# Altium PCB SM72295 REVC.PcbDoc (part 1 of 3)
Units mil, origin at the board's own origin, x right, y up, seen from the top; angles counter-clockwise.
Board outline 8660 x 6340 mil, 6 copper layers (Top Layer, MidLayer1, MidLayer2, MidLayer3, MidLayer4, Bottom Layer), stack 118 mil thick; 253 components, 96 nets, 606 pads, 1472 vias.
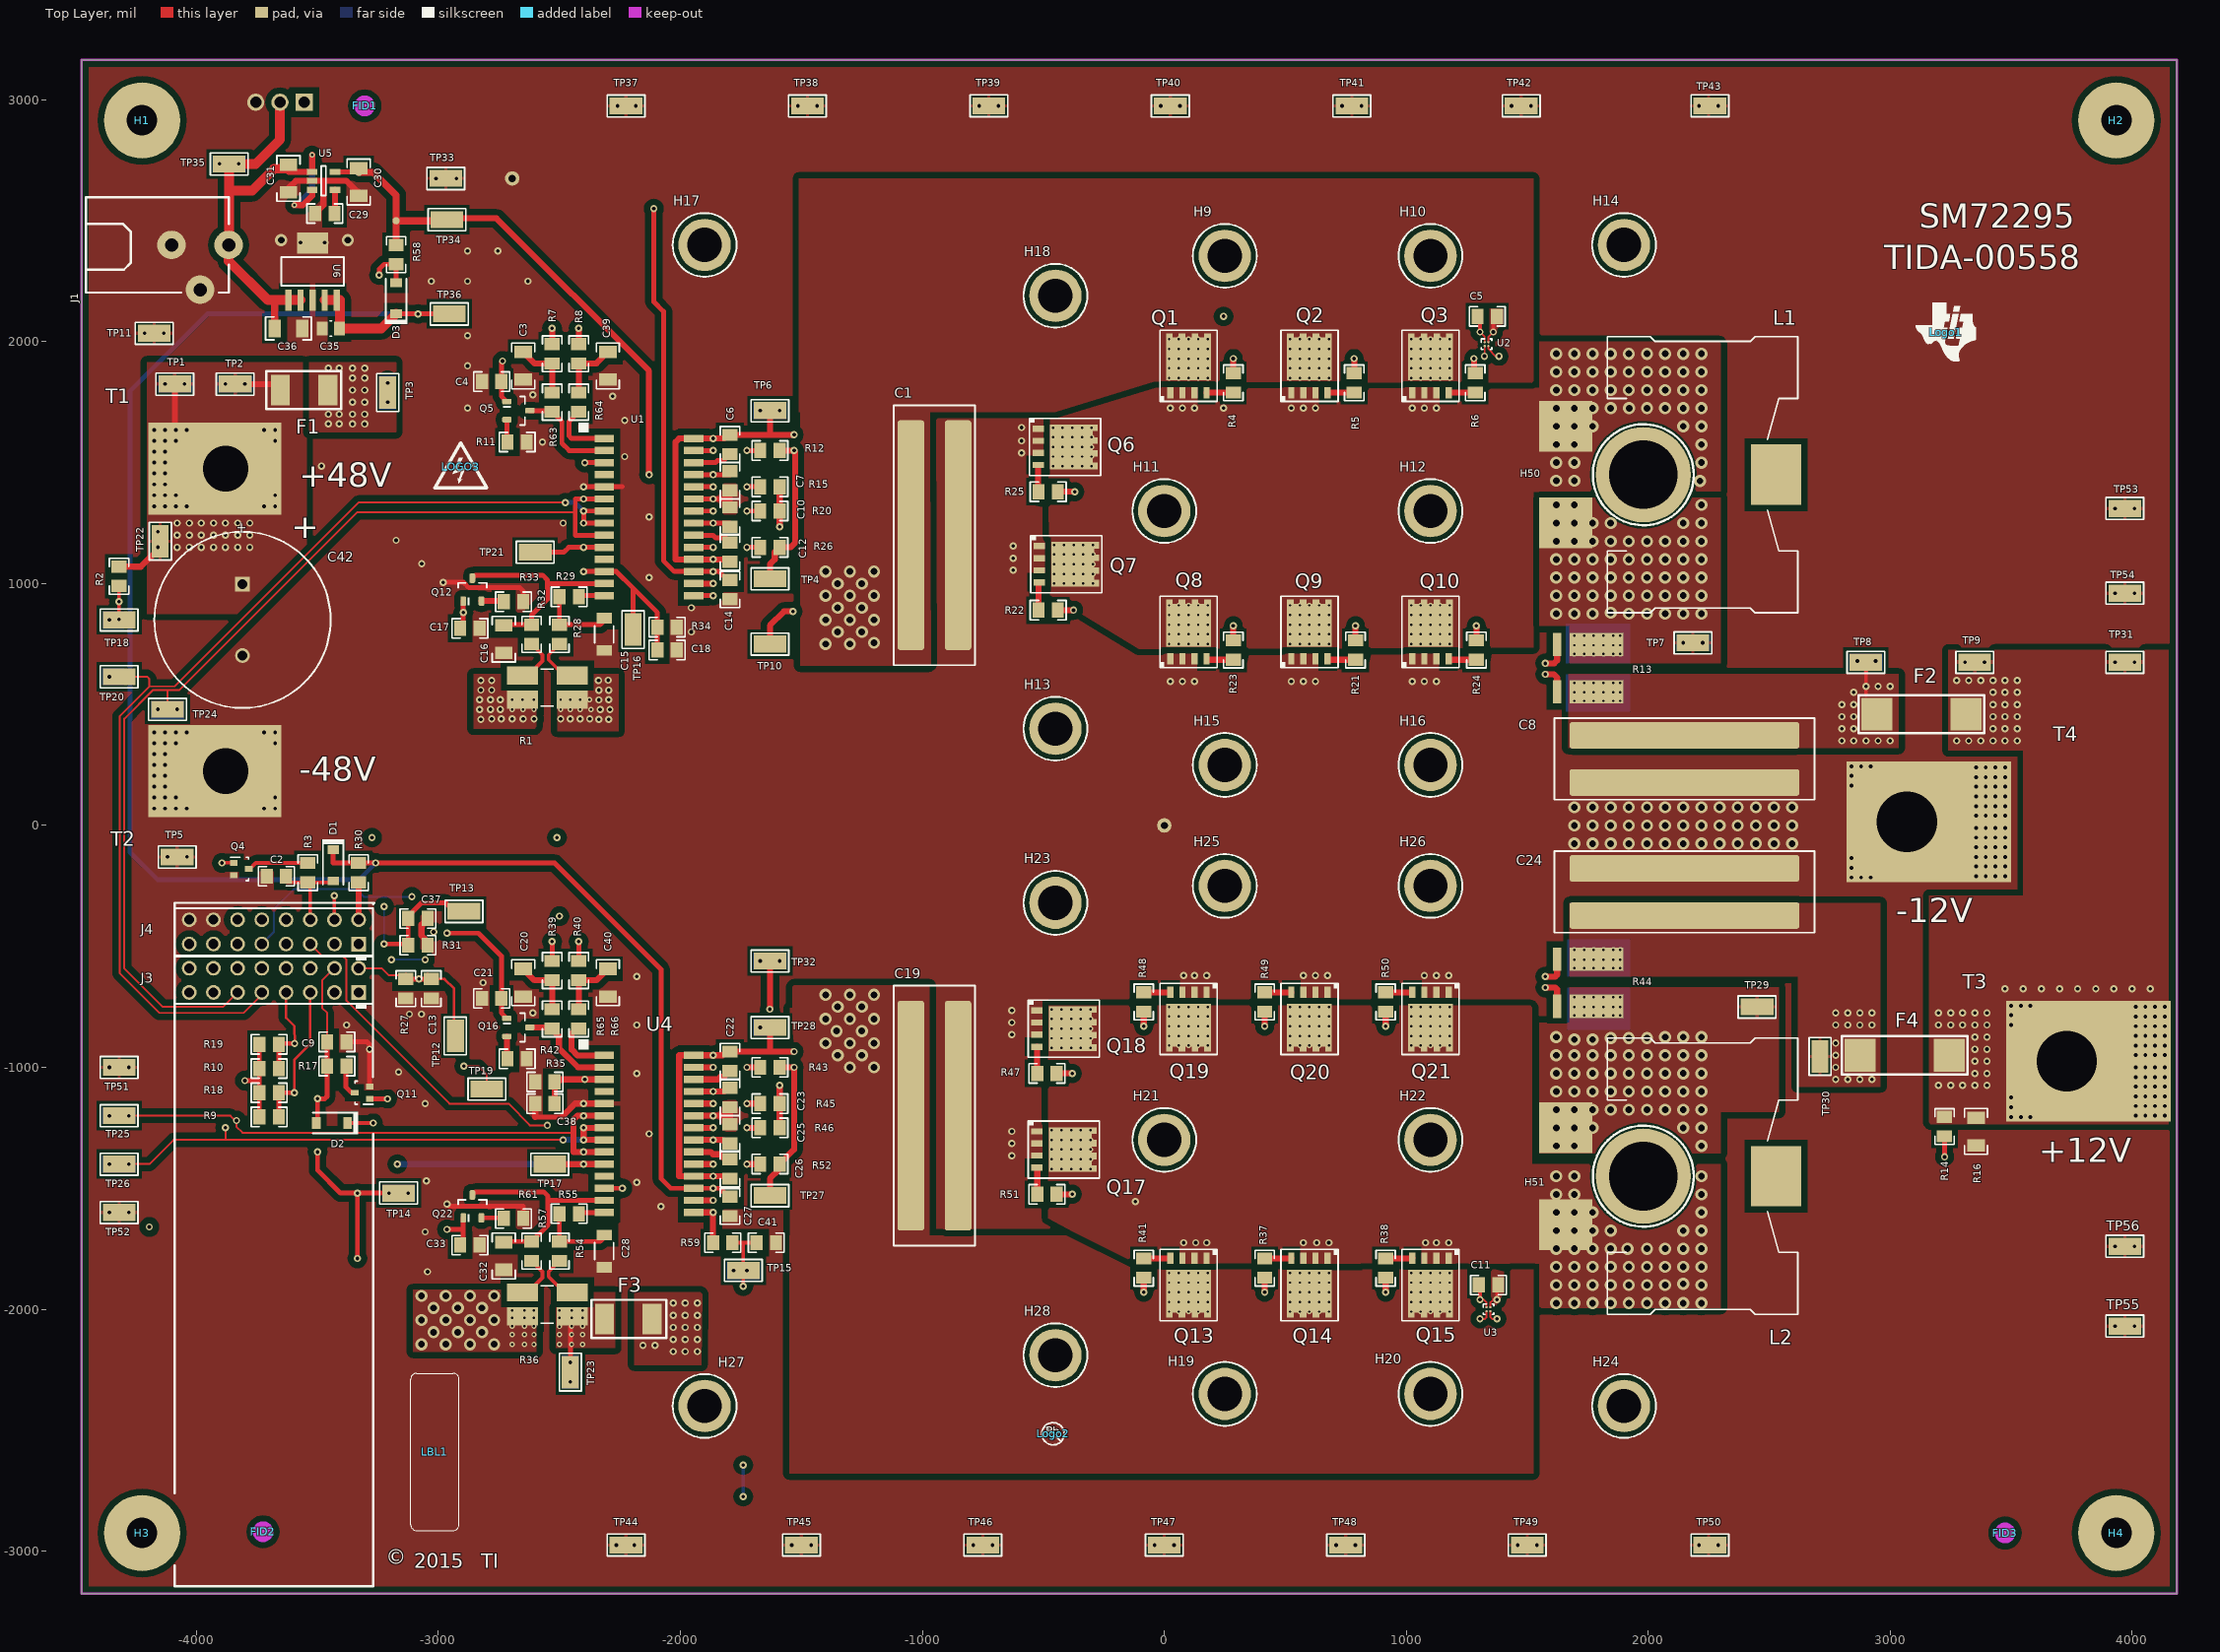
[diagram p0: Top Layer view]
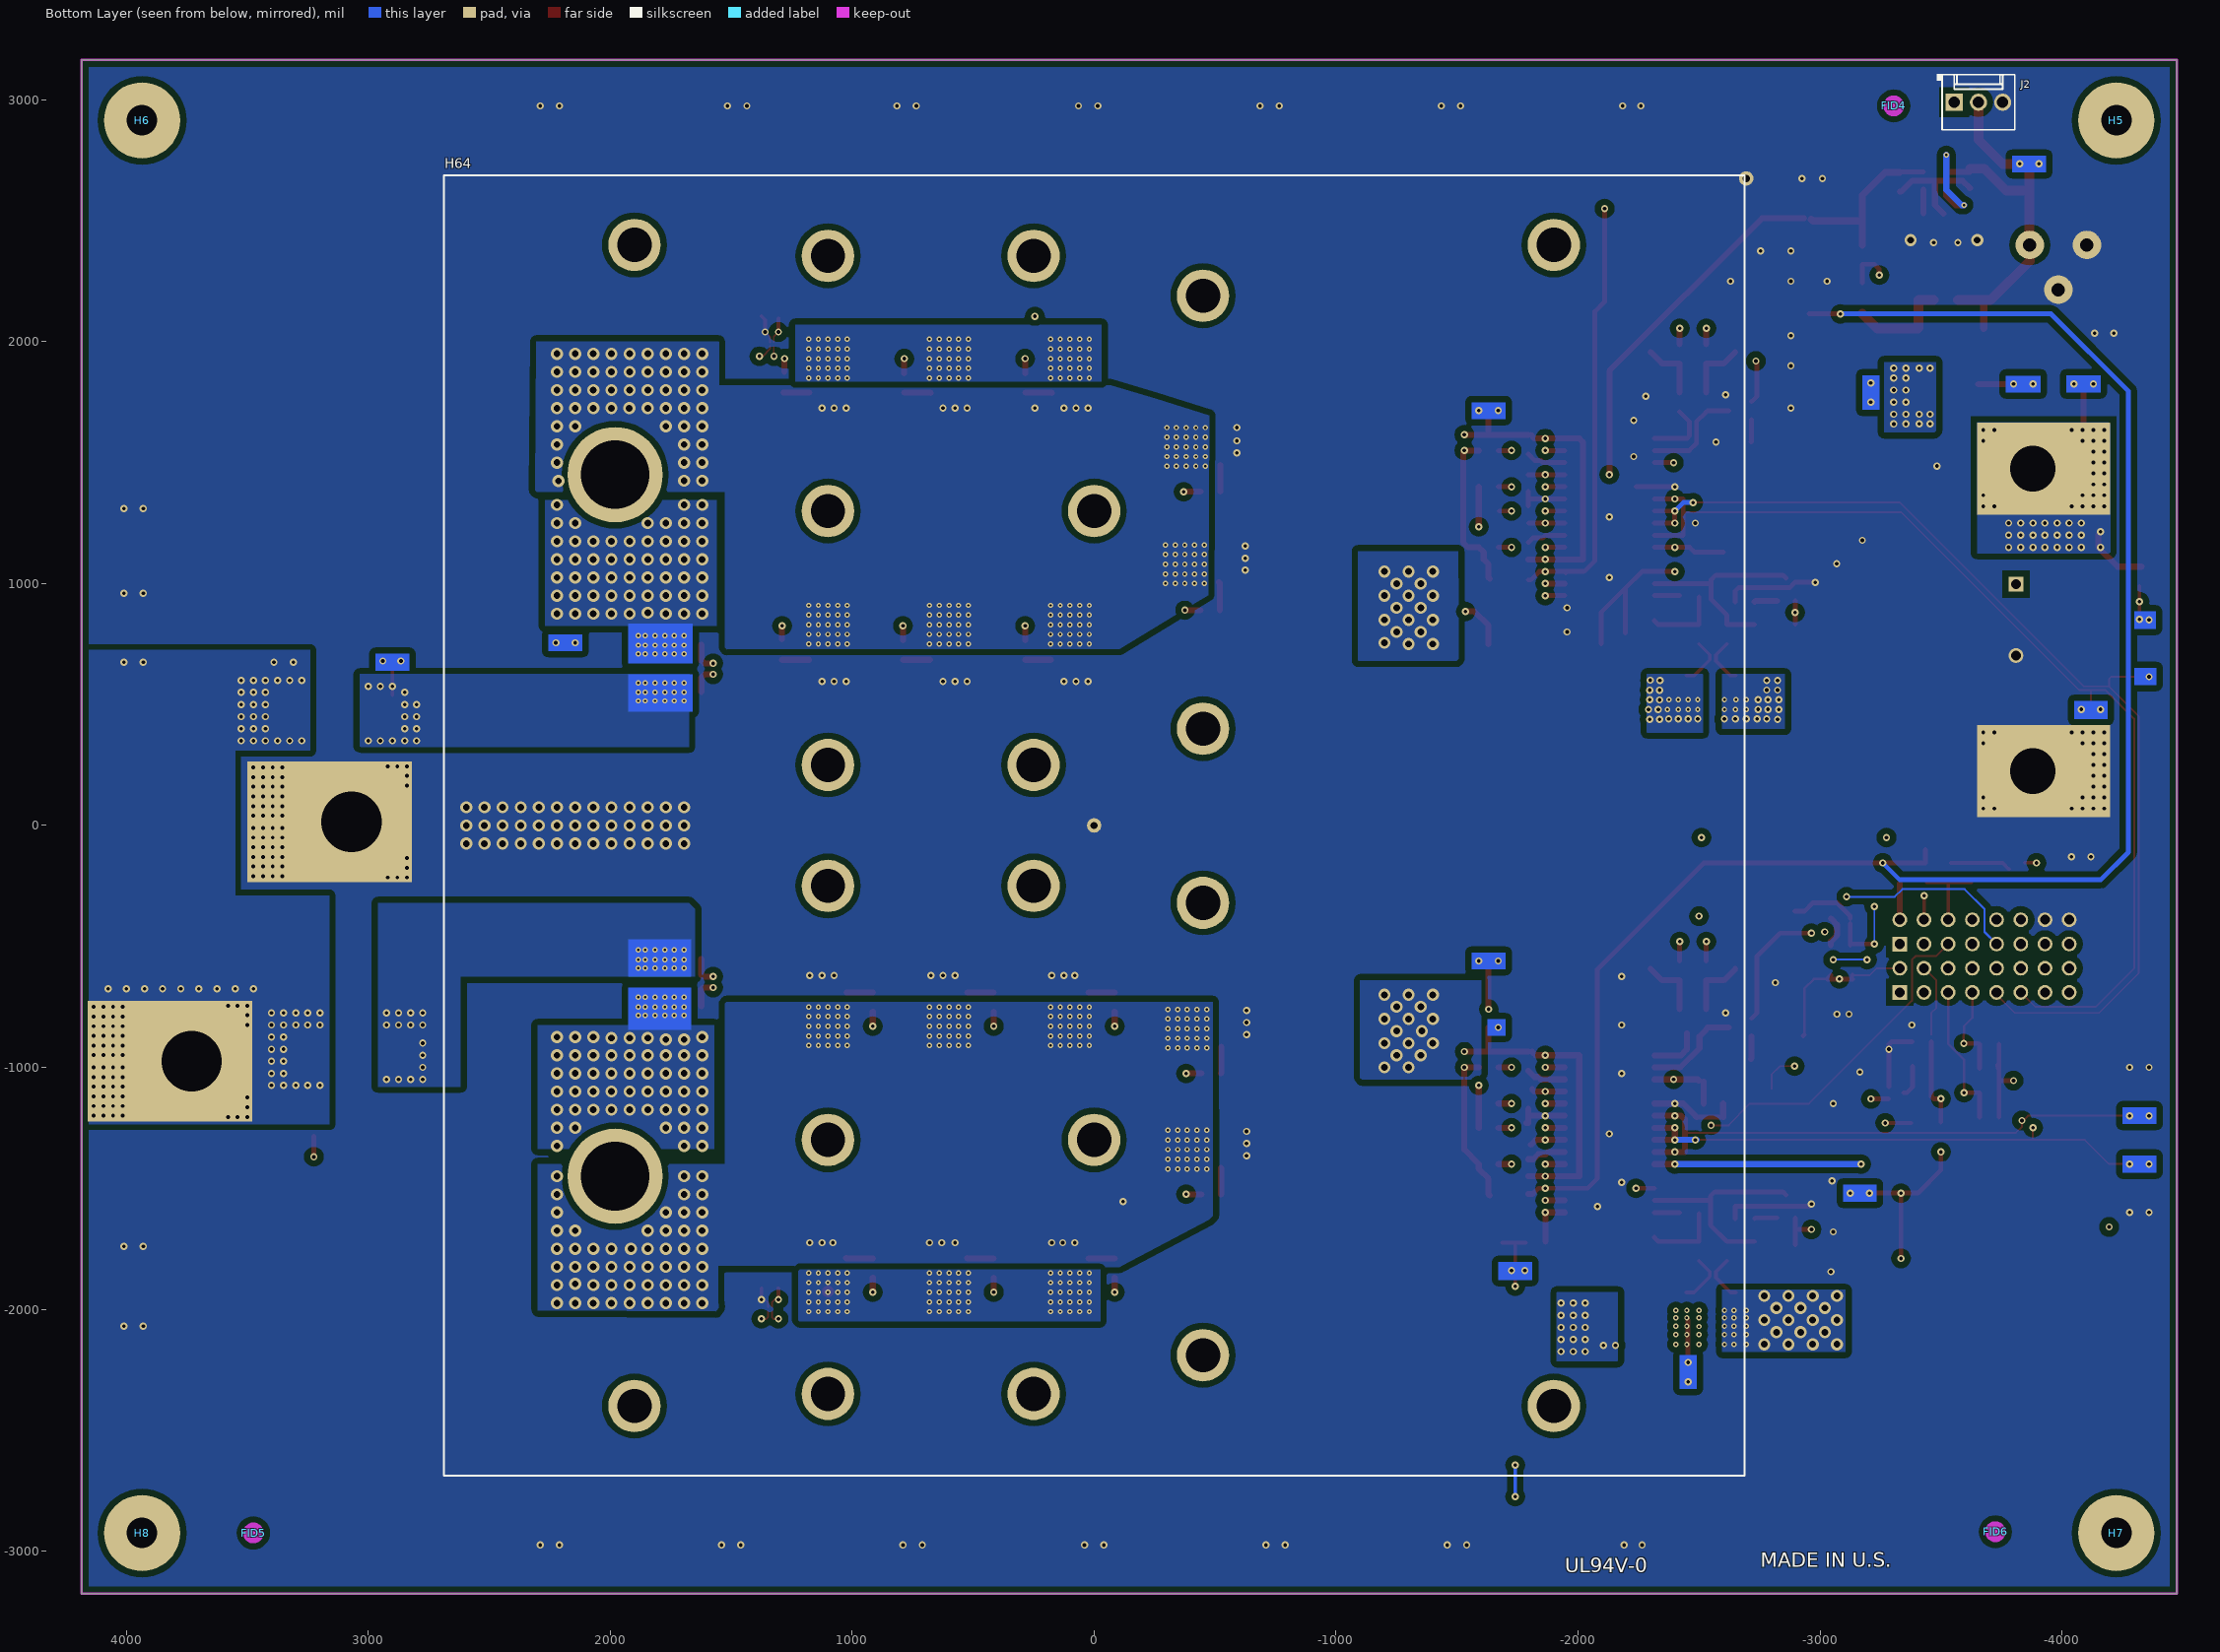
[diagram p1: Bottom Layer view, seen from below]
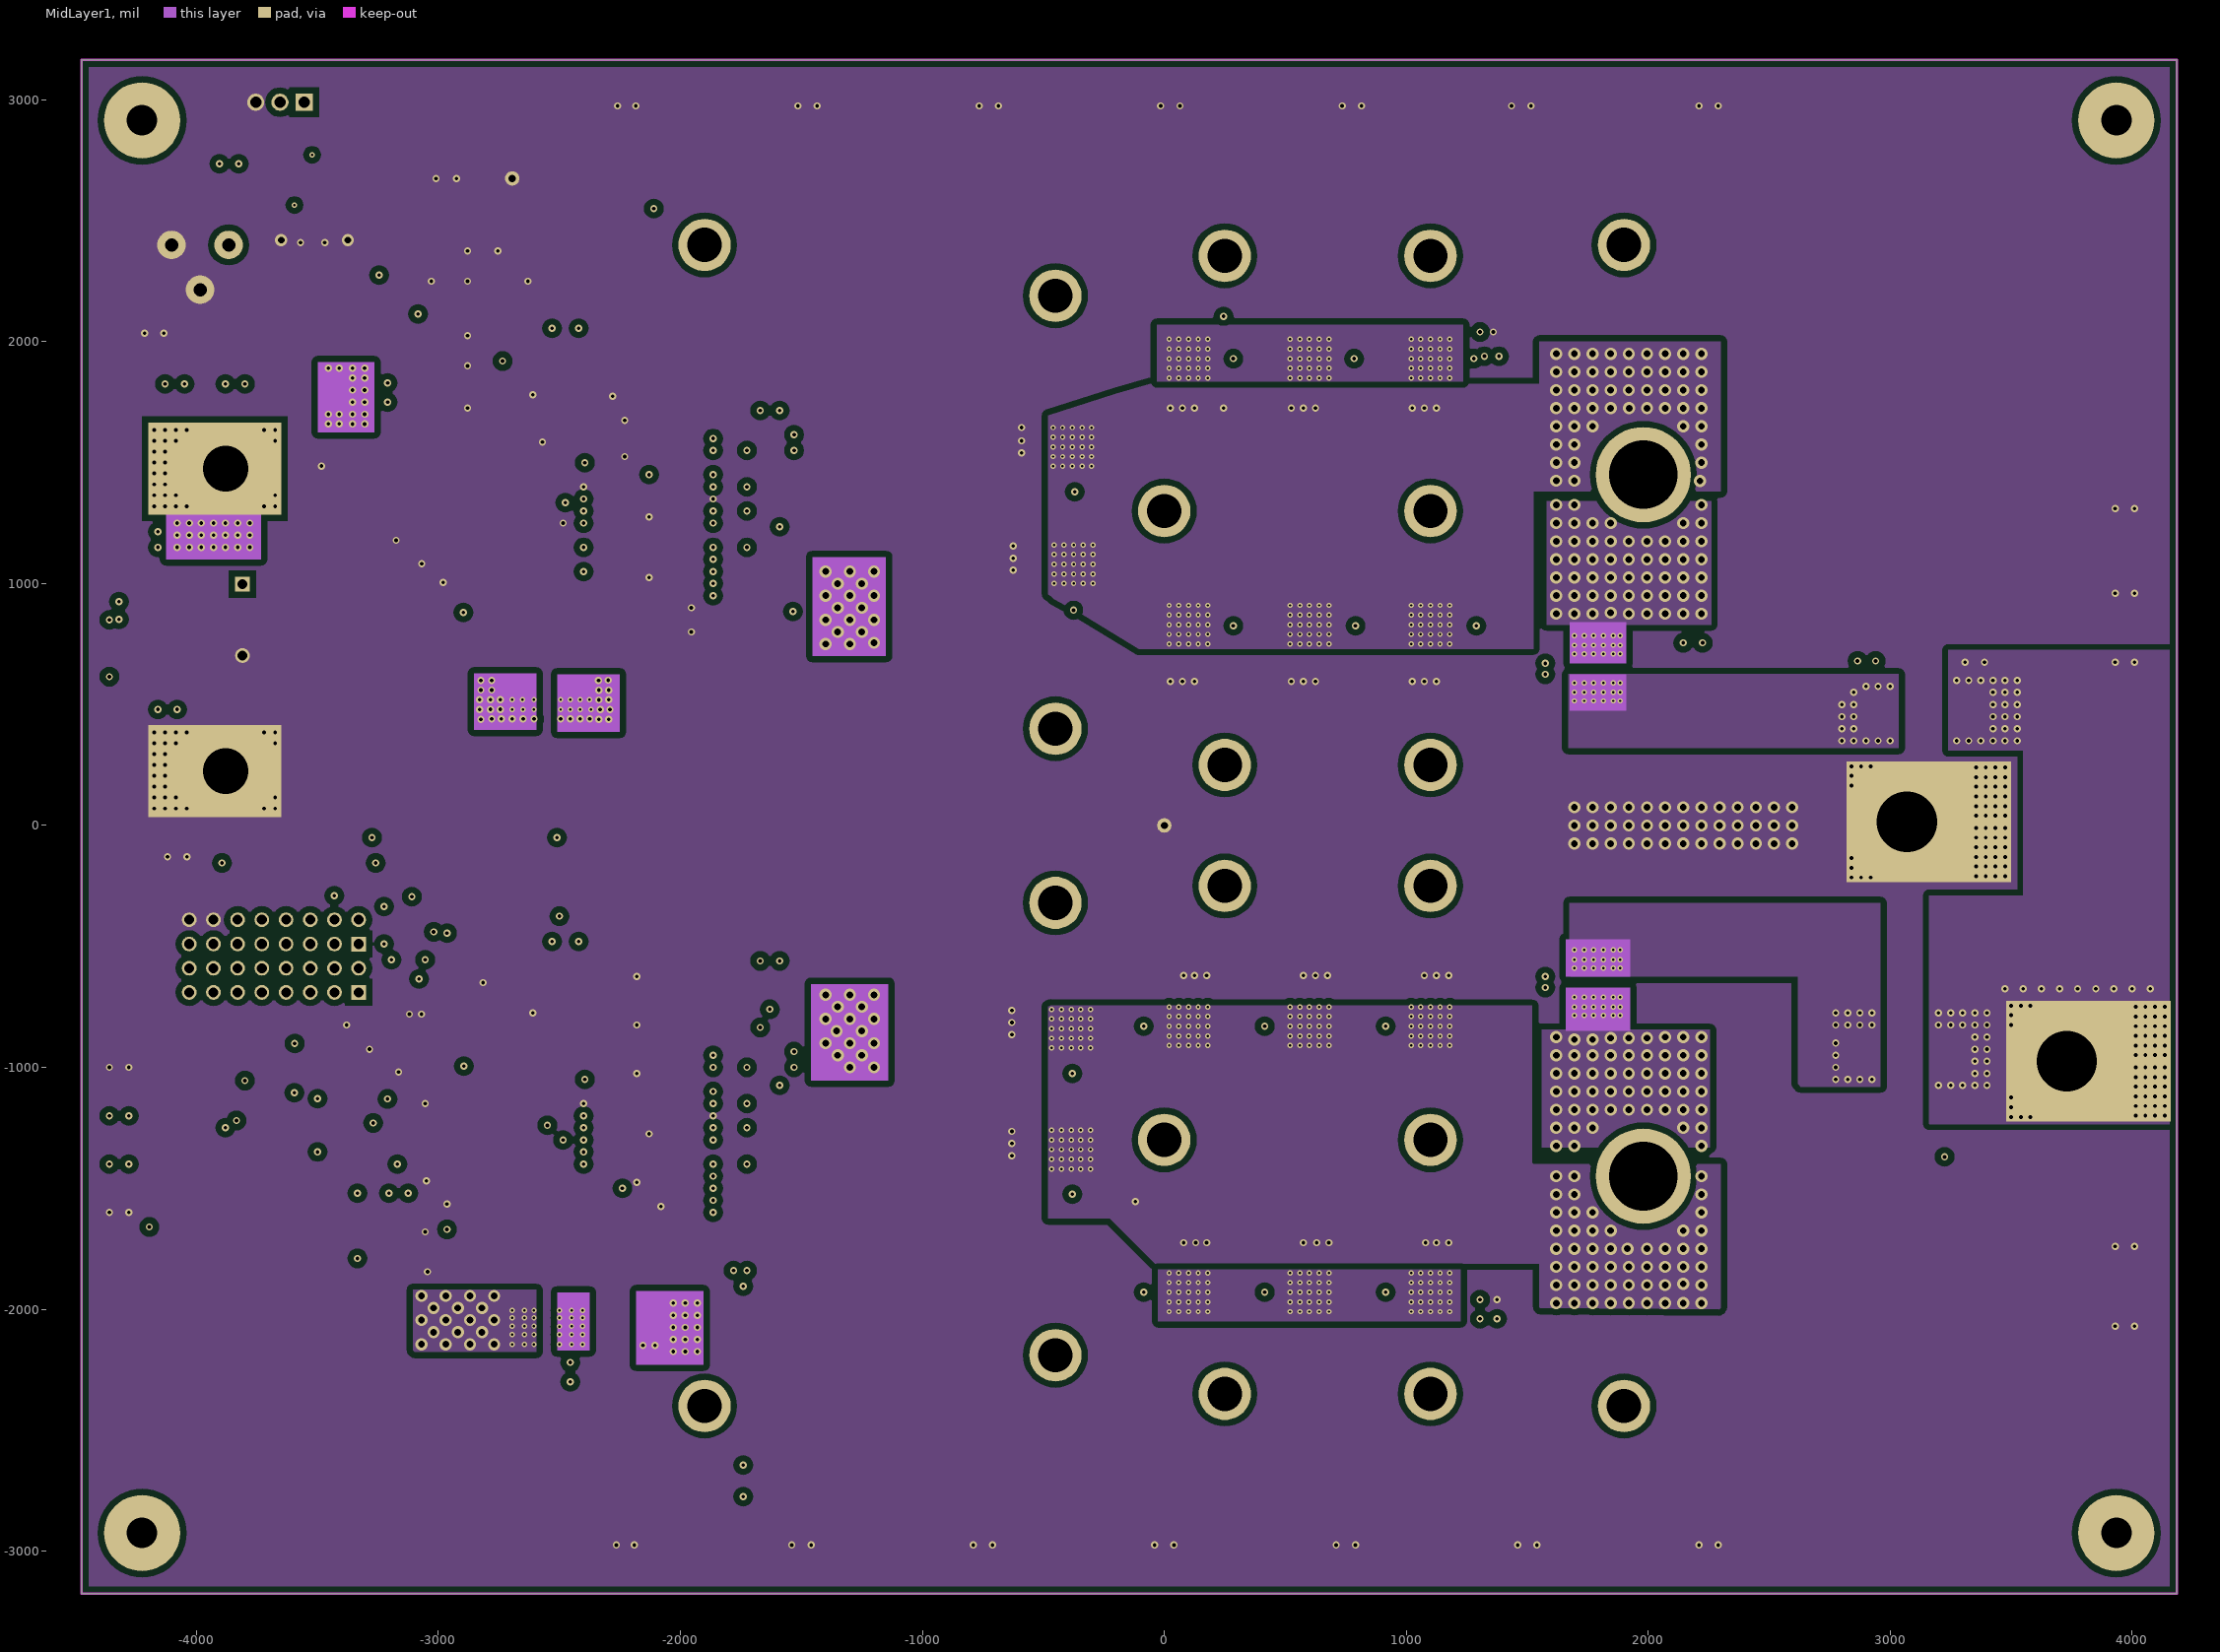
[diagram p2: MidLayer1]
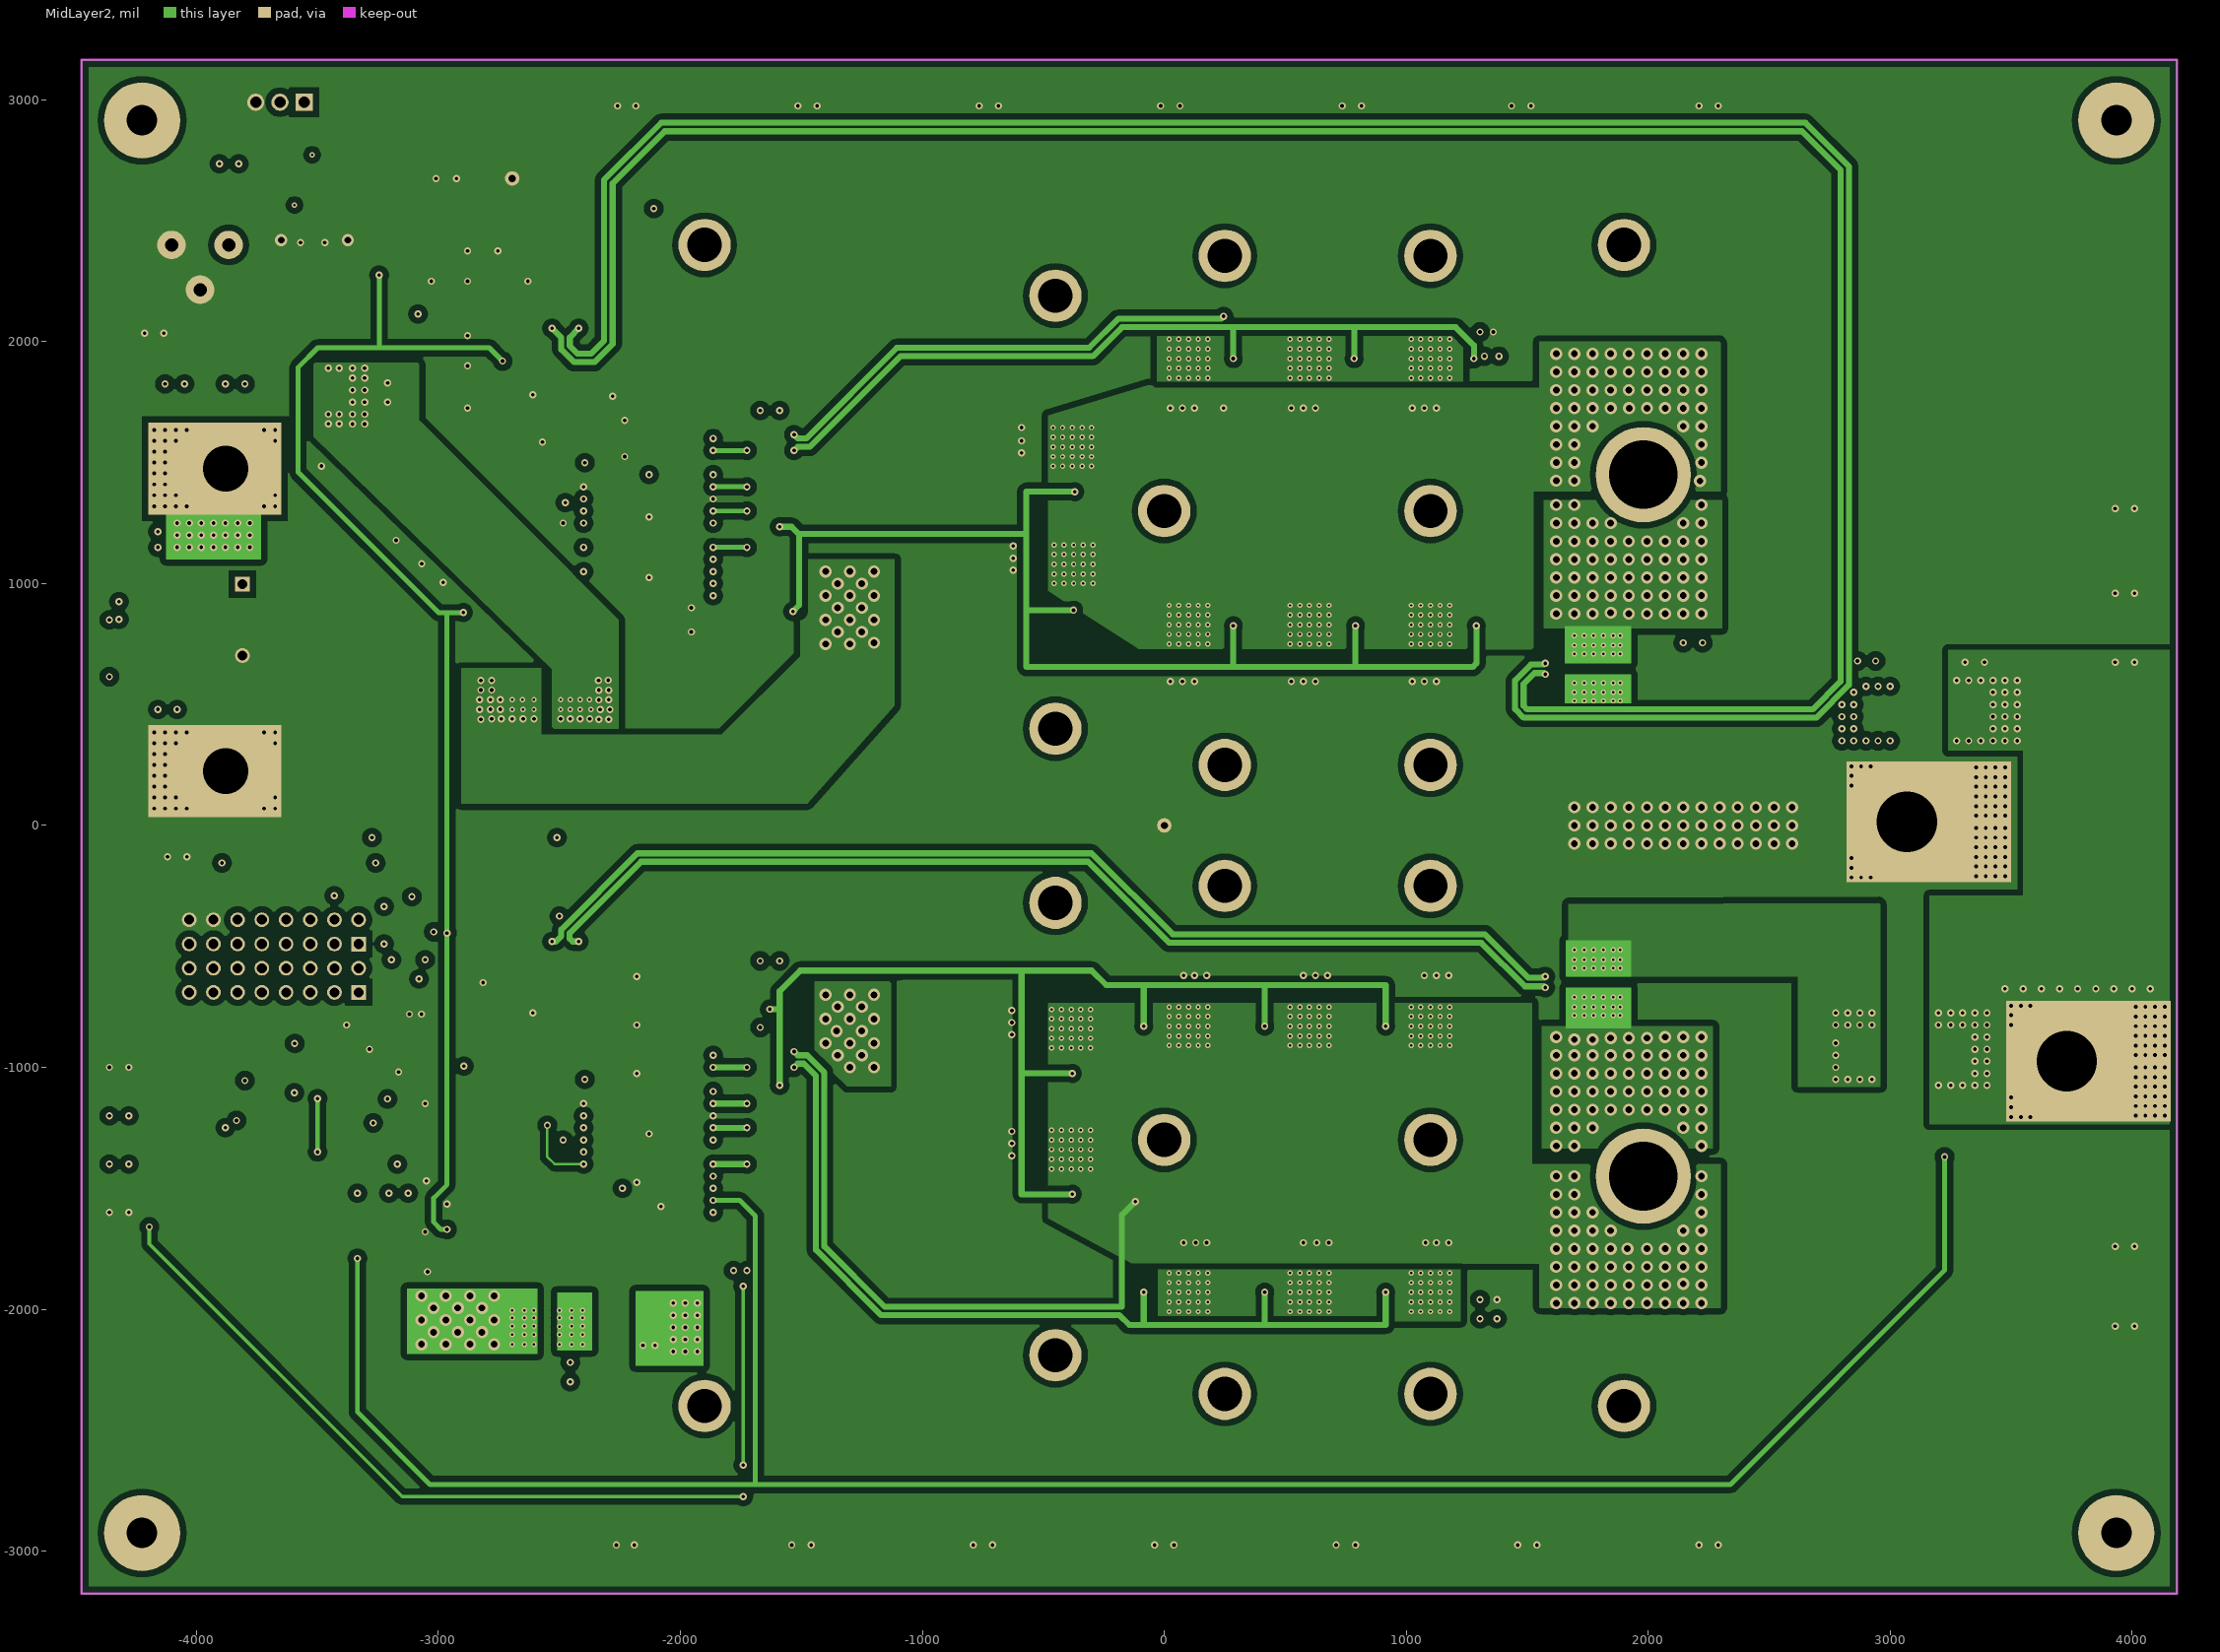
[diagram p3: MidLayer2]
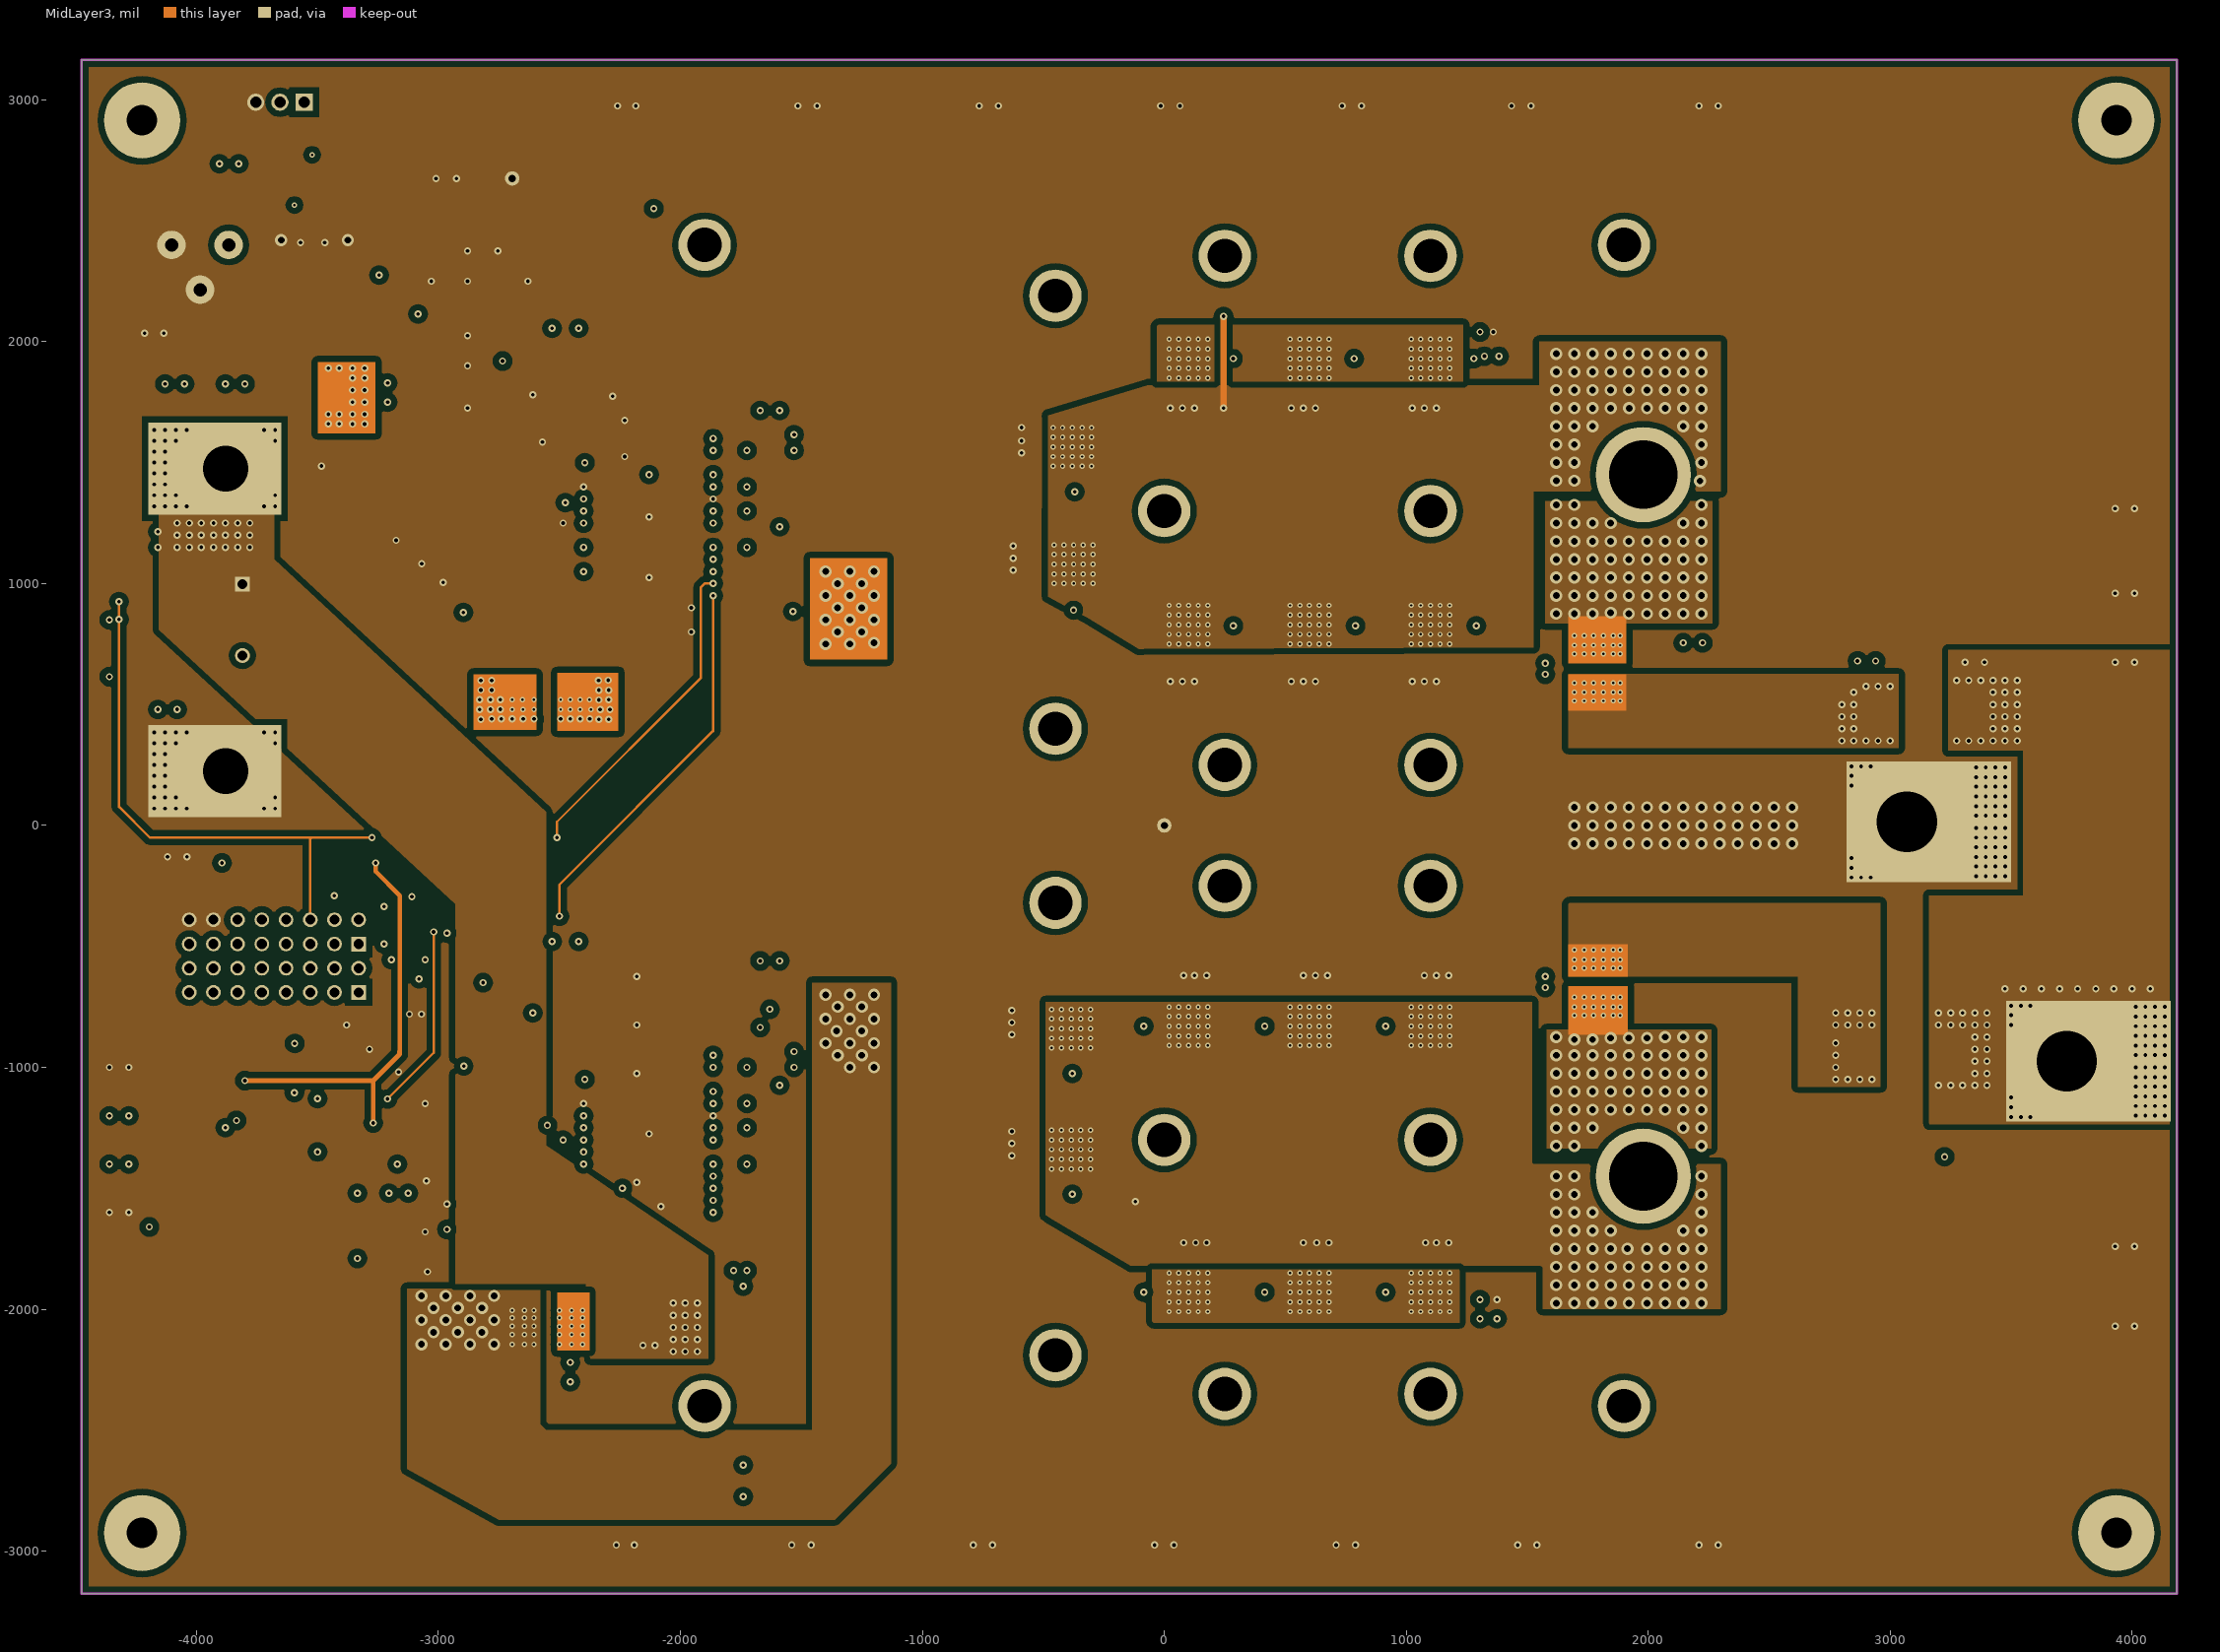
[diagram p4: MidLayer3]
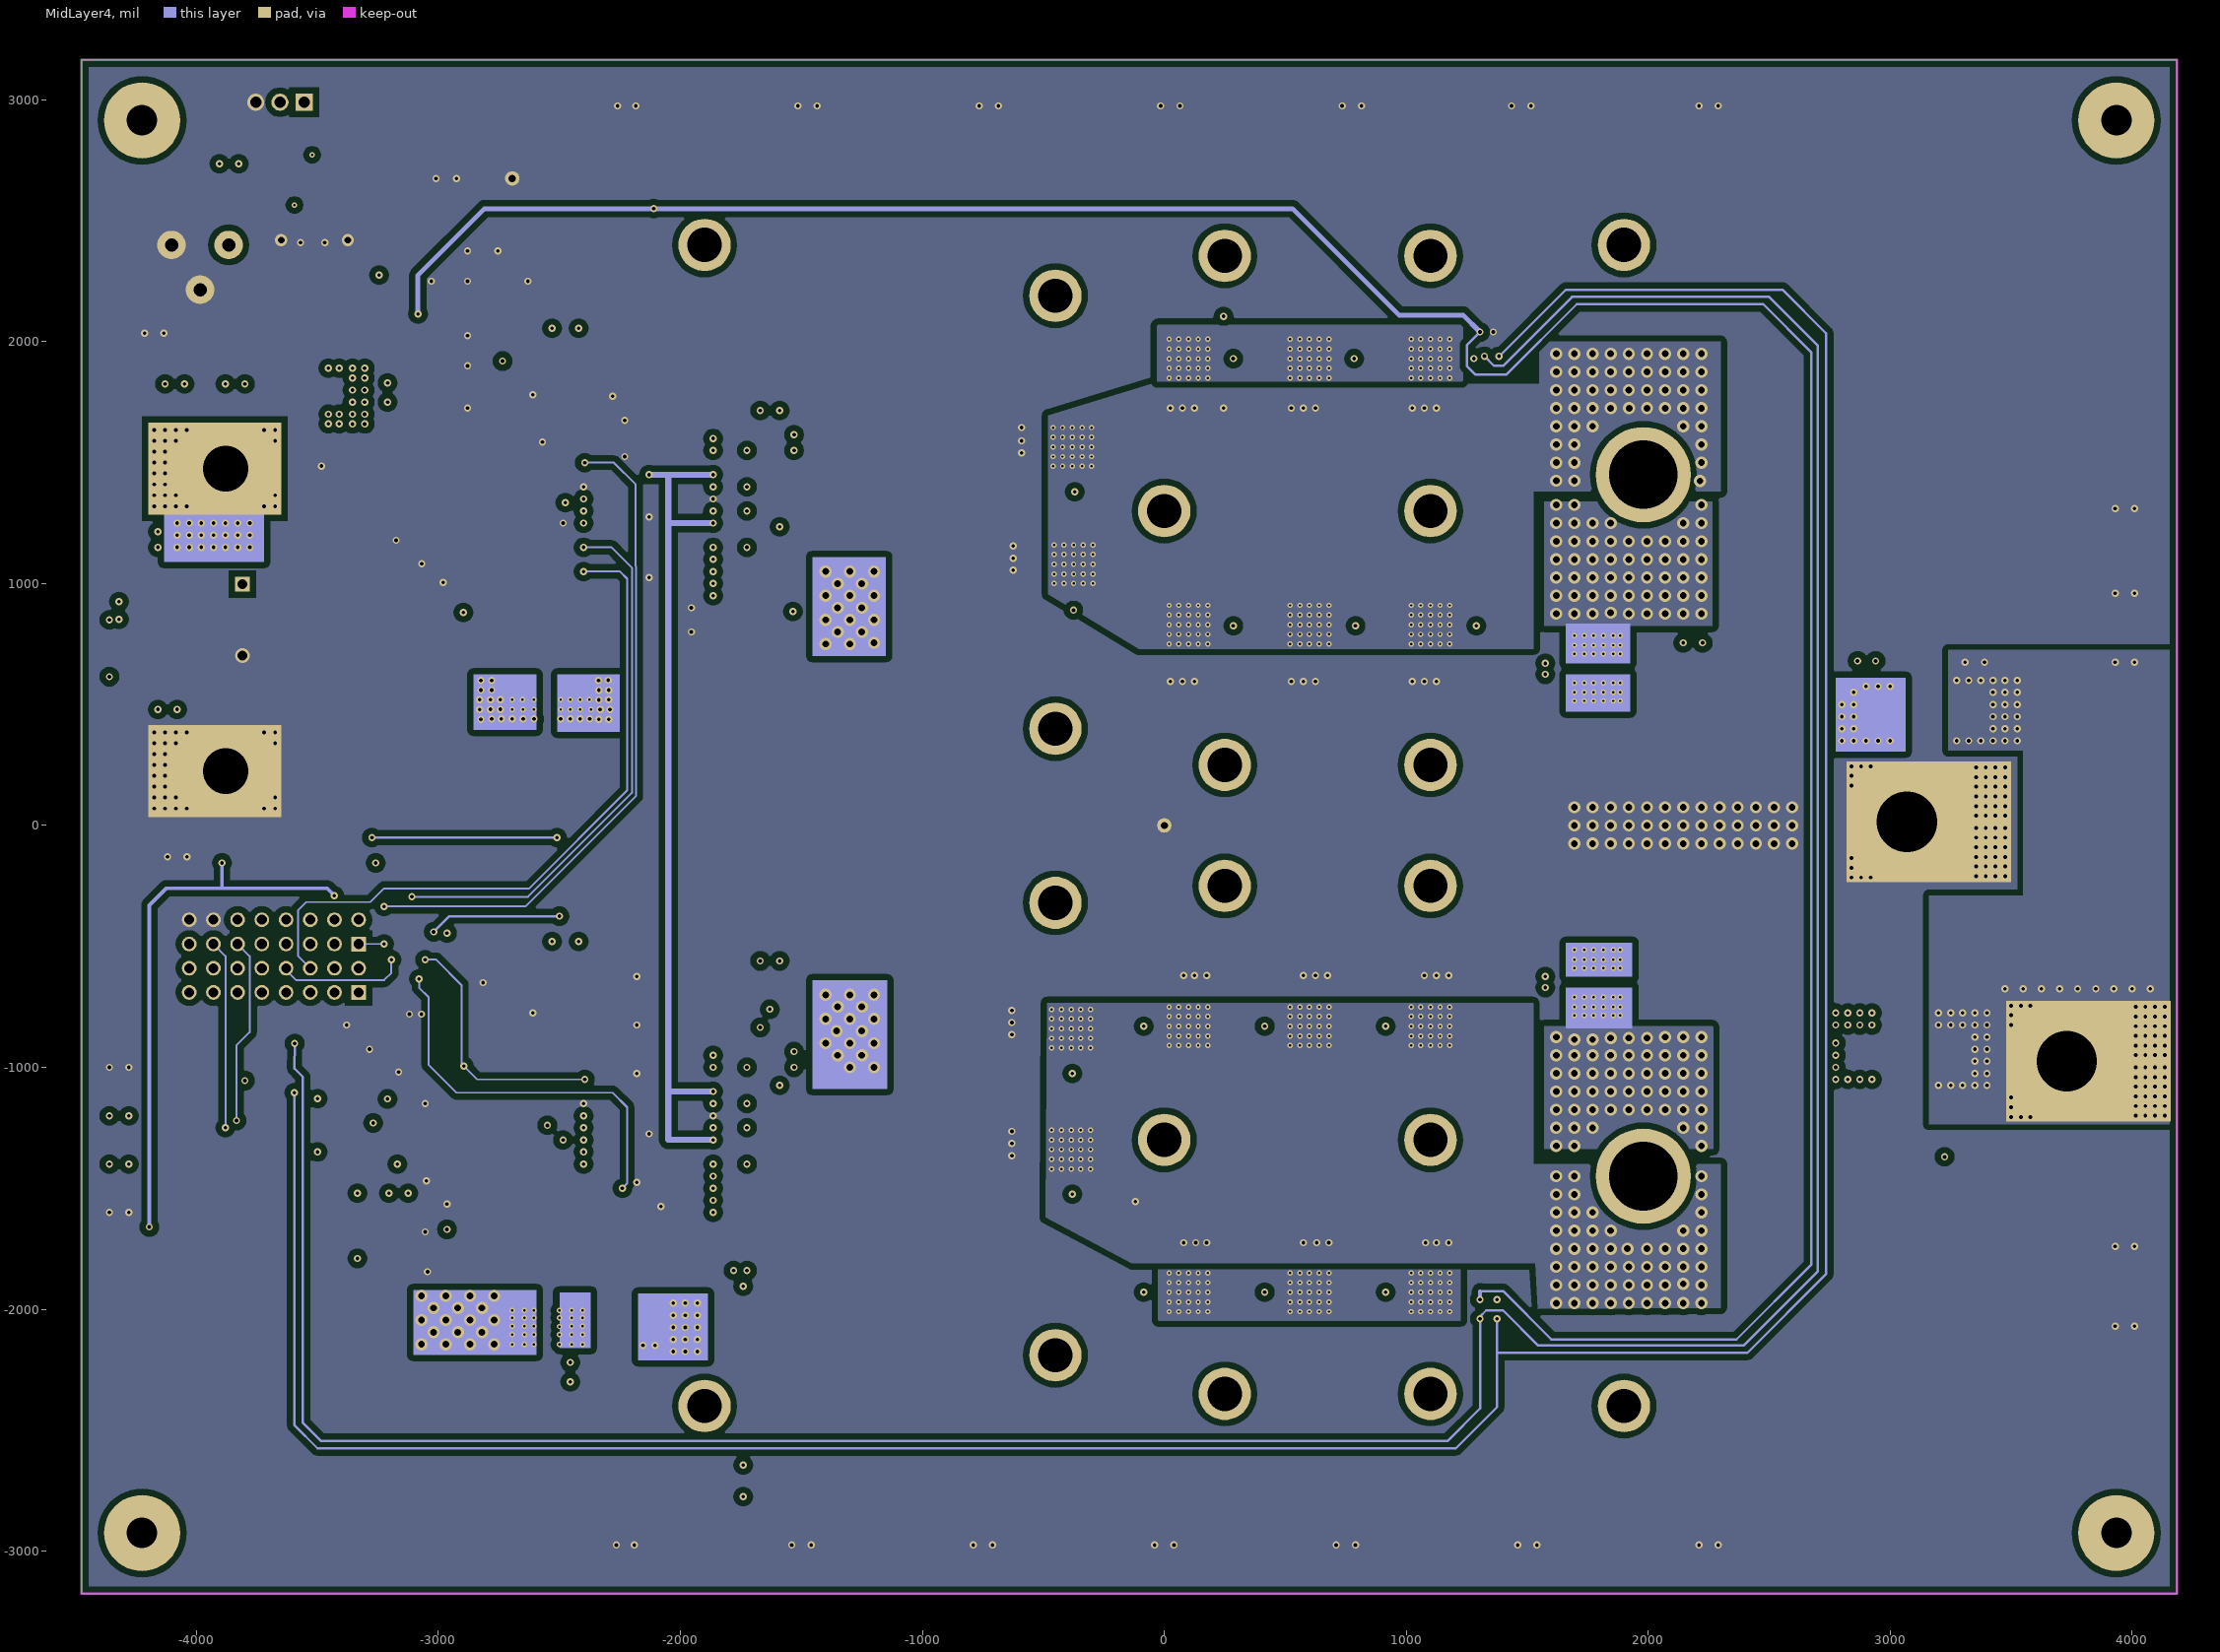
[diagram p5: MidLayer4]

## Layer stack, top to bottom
Top Solder: solder mask 0.4, Solder Resist, Dk 3.5
Top Layer: signal copper 1.4
Dielectric1: core 59.2, FR-4, Dk 4.8
MidLayer1: signal copper 1.4
Dielectric2: prepreg 12.6, FR-4, Dk 4.8
MidLayer2: signal copper 1.4
Dielectric3: core 12.6, FR-4, Dk 4.8
MidLayer3: signal copper 1.4
Dielectric4: prepreg 12.6, FR-4, Dk 4.8
MidLayer4: signal copper 1.4
Dielectric5: core 12.6, FR-4, Dk 4.8
Bottom Layer: signal copper 1.4
Bottom Solder: solder mask 0.4, Solder Resist, Dk 3.5

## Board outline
-4475,-3175 4185,-3175 4185,3165 -4475,3165

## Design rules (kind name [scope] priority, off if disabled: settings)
AcuteAngle [All] p1: minimum=4.50000000000000E+0001 checktracksonly=FALSE
AssemblyTestPointUsage [All] p1: valid=2
Clearance Clearance_BoardEdge_MountingHoles [OnCopper and InComponentClass('Mounting Holes') vs IsKeepOut] p1: gap=40
Clearance Clearance_BoardEdge_Poly [OnCopper and InPoly vs IsKeepOut] p2: gap=25
Clearance Clearance_BoardEdge [OnCopper and Not InComponentClass('Logo') and not InComponentClass('FiducialMark') and not InRegion(1000,500,4000,800) and Not IsKeepout vs IsKeepOut] p3: gap=20
Clearance Clearance_Poly [InPolygon] p4: gap=25
Clearance Clearance_All [All] p5: gap=6.5
ComponentClearance "ComponentClearance_SAMTEC RECEPTACLE" [InComponent('J3') vs InComponent('J4')] p1: gap=0 collisioncheckmode=3 verticalgap=0 showdistances=FALSE
ComponentClearance "ComponentClearance_Screw to Heatsink" [(InComponent('H11') OR InComponent('H12') OR InComponent('H13') OR InComponent('H14') OR InComponent('H15') OR InComponent('H16') OR InComponent('H17') OR InComponent('H18') OR InComponent('H19') OR InComponent('H20') OR InComponent('H21') OR InComponent('H22') OR InComponent('H23') OR InComponent('H24') OR InComponent('H25') OR InComponent('H26') OR InComponent('H27') OR InComponent('H28') OR InComponent('H64') OR InComponent('H9')OR InComponent('H10')) vs InComponent('H64')] p2: gap=0 collisioncheckmode=3 verticalgap=0 showdistances=FALSE
ComponentClearance ComponentClearance_Shunt [InComponentClass('Header') vs InComponentClass('Shunt')] p3: gap=0 collisioncheckmode=3 verticalgap=0 showdistances=FALSE
ComponentClearance ComponentClearance_MountingHoles_FiducialMarks [InComponentClass('Mounting Holes') vs InComponentClass('FiducialMark')] p4: gap=50 collisioncheckmode=3 verticalgap=10 showdistances=FALSE
ComponentClearance ComponentClearance_Logo [InComponentClass('Logo')] p5: gap=50 collisioncheckmode=3 verticalgap=10 showdistances=FALSE
ComponentClearance ComponentClearance_ScrewToNut [(HasFootprint('NY PMS 440 0025 PH')) vs (HasFootprint('Keystone_1902C'))] p6: gap=5 collisioncheckmode=3 verticalgap=10 showdistances=FALSE
ComponentClearance ComponentClearance_MountingHoles [InComponentClass('Mounting Holes')] p7: gap=250 collisioncheckmode=3 verticalgap=100000 showdistances=FALSE
ComponentClearance ComponentClearance_SmallPassives [HasFootprint('0201*') or HasFootprint('0402*') or HasFootprint('0508') or HasFootprint('0603*') or HasFootprint('0612') or HasFootprint('0805*') or HasFootprint('0815*') or HasFootprint('0830*') or HasFootprint('1206*') or HasFootprint('1210*') or HasFootprint('1808*') or HasFootprint('1812*') or HasFootprint('1825*') or HasFootprint('2010*') or HasFootprint('2220*') or HasFootprint('2225*') or HasFootprint('2512*') or HasFootprint('2728*') or HasFootprint('3518*') vs HasFootprint('0201*') or HasFootprint('0402*') or HasFootprint('0508') or HasFootprint('0603*') or HasFootprint('0612') or HasFootprint('0805*') or HasFootprint('0815*') or HasFootprint('0830*') or HasFootprint('1206*') or HasFootprint('1210*') or HasFootprint('1808*') or HasFootprint('1812*') or HasFootprint('1825*') or HasFootprint('2010*') or HasFootprint('2220*') or HasFootprint('2225*') or HasFootprint('2512*') or HasFootprint('2728*') or HasFootprint('3518*')] p8: gap=20 collisioncheckmode=3 verticalgap=10 showdistances=FALSE
ComponentClearance ComponentClearance_THtoSMT [IsThruComponent vs IsSMTComponent] p9: gap=100 collisioncheckmode=3 verticalgap=30 showdistances=FALSE
ComponentClearance ComponentClearance_THtoTH [IsThruComponent vs IsThruComponent] p10: gap=118.11 collisioncheckmode=3 verticalgap=30 showdistances=FALSE
ComponentClearance [All] p11: gap=40 collisioncheckmode=3 verticalgap=10 showdistances=FALSE
DiffPairsRouting [All] p1: maxlimit=100 minlimit=10 mostfreqgap=10 toplayer_minwidth=15 toplayer_maxwidth=15 toplayer_prefwidth=15 midlayer1_minwidth=15 midlayer1_maxwidth=15 midlayer1_prefwidth=15 midlayer2_minwidth=15 midlayer2_maxwidth=15 midlayer2_prefwidth=15 midlayer3_minwidth=15 midlayer3_maxwidth=15 midlayer3_prefwidth=15 midlayer4_minwidth=15 midlayer4_maxwidth=15 midlayer4_prefwidth=15 bottomlayer_minwidth=15 bottomlayer_maxwidth=15 bottomlayer_prefwidth=15 maxuncoupledlength=1000
FabricationTestPointUsage TestPointUsage [All] p1: valid=2 allowmultiple=FALSE
FabricationTestpoint Testpoint [All] p1: side=3 testpointundercomponent=TRUE minsize=40 maxsize=100 preferedsize=60 minholesize=0 maxholesize=40 preferedholesize=32 testpointgrid=1 allowsidetop=TRUE allowsidebottom=TRUE usegrid=TRUE gridtolerance=0.01
FanoutControl Fanout_LCC [IsLCC] p1: bgadir=Out bgaviamode=Centered fanoutstyle=Auto fanoutdirection=Alternating viagrid=1 // Fanout_LCC (Default Rule)
FanoutControl Fanout_BGA [IsBGA] p2: bgadir=Out bgaviamode=Centered fanoutstyle=Auto fanoutdirection=Alternating viagrid=1 // Fanout_BGA (Default Rule)
FanoutControl Fanout_Default [All] p4: bgadir=Out bgaviamode=Centered fanoutstyle=Auto fanoutdirection=Alternating viagrid=1 // Fanout_Default (Default Rule)
FanoutControl Fanout_Small [(CompPinCount < 5)] p5: bgadir=Out bgaviamode=Centered fanoutstyle=Auto fanoutdirection=OutThenIn viagrid=1 // Fanout_Small (Default Rule)
HoleSize [All] p1: absolutevalues=TRUE maxlimit=250 minlimit=10 maxpercent=80.000 minpercent=20.000
MinimumAnnularRing MinimumAnnularRing_ThermalPadVias [IsVia and InAnyComponent] p1: minimumring=6
MinimumAnnularRing [All] p2: minimumring=6
MinimumSolderMaskSliver MinimumSolderMaskSliver_Logo [InComponentClass('Logo') vs InComponentClass('Logo')] p1: minsoldermaskwidth=0.7
MinimumSolderMaskSliver [All] p2: minsoldermaskwidth=3.94
PlaneConnect [All] p1: planeconnectstyle=Relief reliefexpansion=10 reliefentries=4 reliefconductorwidth=10 reliefairgap=10
PolygonConnect "PolygonConnect_Test Pins" [HasFootprint('Testpoint_Keystone_Miniature')] p1: connectstyle=Relief reliefconductorwidth=15 reliefentries=4 polygonreliefangle="90 Angle" airgapwidth=10
PolygonConnect PolygonConnect_All [All] p2: connectstyle=Direct reliefconductorwidth=10 reliefentries=4 polygonreliefangle="90 Angle" airgapwidth=10
RoutingVias ThermalPadVias [IsVia and InAnyComponent] p1: holewidth=16 width=34 viastyle="Through Hole" minholewidth=10 minwidth=22 maxholewidth=40 maxwidth=65
RoutingVias [All] p2: holewidth=16 width=34 viastyle="Through Hole" minholewidth=10 minwidth=22 maxholewidth=40 maxwidth=65
SMDToCorner [All] p1: distance=30000
SilkToSilkClearance SilkToSilkClearance_Pb-FreeLogo [(HasFootprint('Pb-Free_Overlay_Medium') OR HasFootprint('Pb-Free_Overlay_Small')) vs (HasFootprint('Pb-Free_Overlay_Medium') OR HasFootprint('Pb-Free_Overlay_Small'))] p1: silktosilkclearance=0
SilkToSilkClearance [All] p2: silktosilkclearance=5
SilkToSolderMaskClearance SilkscreenOverComponentPads [IsPad] p1: minsilkscreentomaskgap=5 clearancetoexposedcopper=TRUE
SolderMaskExpansion [All] p1: expansion=1.97
UnpouredPolygon [All] p1: allowunpoured=FALSE
Width Width_48_2_P [InNet('V48_2_P')] p1: maxlimit=15 minlimit=15 preferedwidth=15
Width Width_48_2_N [InNet('V48_2_N')] p2: maxlimit=15 minlimit=15 preferedwidth=15
Width Width_48_1_P [InNet('V48_1_P')] p3: maxlimit=15 minlimit=15 preferedwidth=15
Width Width_48_1_N [InNet('V48_1_N')] p4: maxlimit=15 minlimit=15 preferedwidth=15
Width Width_SIAP2_N [InNet('SIAP2_N')] p5: maxlimit=25 minlimit=10 preferedwidth=25
Width Width_SIAP2_P [InNet('SIAP2_P')] p6: maxlimit=25 minlimit=10 preferedwidth=25
Width Width_LOGATEBP2 [InNet('LOGATEBP2')] p7: maxlimit=25 minlimit=10 preferedwidth=25
Width Width_LOGATEAP2 [InNet('LOGATEAP2')] p8: maxlimit=25 minlimit=10 preferedwidth=25
Width Width_HIGATEAP2_N [InNet('HIGATEAP2_N')] p9: maxlimit=25 minlimit=10 preferedwidth=25
Width Width_HIGATEAP2_P [InNet('HIGATEAP2_P')] p10: maxlimit=25 minlimit=10 preferedwidth=25
Width Width_HG2A_N [InNet('HG2A_N')] p11: maxlimit=25 minlimit=25 preferedwidth=25
Width Width_HG1A_N [InNet('HG1A_N')] p12: maxlimit=25 minlimit=25 preferedwidth=25
Width Width_HG2A_P [InNet('HG2A_P')] p13: maxlimit=25 minlimit=25 preferedwidth=25
Width Width_HG1A_P [InNet('HG1A_P')] p14: maxlimit=25 minlimit=25 preferedwidth=25
Width Width_LOGATEBP1 [InNet('LOGATEBP1')] p15: maxlimit=25 minlimit=10 preferedwidth=25
Width Width_LOGATEAP1 [InNet('LOGATEAP1')] p16: maxlimit=25 minlimit=10 preferedwidth=25
Width Width_SIAP1_N [InNet('SIAP1_N')] p17: maxlimit=25 minlimit=10 preferedwidth=25
Width Width_SIAP1_P [InNet('SIAP1_P')] p18: maxlimit=25 minlimit=10 preferedwidth=25
Width [All] p19: maxlimit=100 minlimit=6 preferedwidth=10 checkconnectedcopper=TRUE
15 further rules are at their usual default settings.

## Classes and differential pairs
component class Hardware_ANSI-B: FID1 FID2 FID3 FID4 FID5 FID6 H1 H2 H3 H4 H5 H6 H7 H8 H9 H10 H11 H12 H13 H14 H15 H16 H17 H18 H19 H20 H21 H22 H23 H24 H25 H26 H27 H28 H50 H51 H64 LBL1 Logo1 Logo2 LOGO3 ZZ1 ZZ2 ZZ3 ZZ4 ZZ5 ZZ6 ZZ7 ZZ8
component class "SM72295Eval REV 27 Mod": 60 C1 C2 C3 C4 C5 C6 C7 C8 C9 C10 C11 C12 C13 C14 C15 C16 C17 C18 C19 C20 C21 C22 C23 C24 C25 C26 C27 C28 C29 C30 C31 C32 C33 C35 C36 C37 C38 C39 C40 C41 C42 D1 D2 D3 F1 F2 F3 F4 J1 J2 J3 J4 L1 L2 Q1 Q2 Q3 Q4 Q5 Q6 Q7 Q8 Q9 Q10 Q11 Q12 Q13 Q14 Q15 Q16 Q17 Q18 Q19 Q20 Q21 Q22 R1 R2 R3 R4 R5 R6 R7 R8 R9 R10 R11 R12 R13 R14 R15 R16 R17 R18 R19 R20 R21 R22 R23 R24 R25 R26 R27 R28 R29 R30 R31 R32 R33 R34 R35 R36 R37 R38 R39 R40 R41 R42 R43 R44 R45 R46 R47 R48 R49 R50 R51 R52 R54 R55 R57 R58 R59 R61 R63 R64 R65 R66 R68 R69 R73 T1 T2 T3 T4 TP1 TP2 TP3 TP4 TP5 TP6 TP7 TP8 TP9 TP10 TP11 TP12 TP13 TP14 TP15 TP16 TP17 TP18 TP19 TP20 TP21 TP22 TP23 TP24 TP25 TP26 TP27 TP28 TP29 TP30 TP31 TP32 TP33 TP34 TP35 TP36 TP37 TP38 TP39 TP40 TP41 TP42 TP43 TP44 TP45 TP46 TP47 TP48 TP49 TP50 TP51 TP52 TP53 TP54 TP55 TP56 U1 U2 U3 U4 U5 U6 U8
differential pair SIAP2: +SIAP2_P -SIAP2_N
differential pair SIAP1: +SIAP1_P -SIAP1_N
differential pair V48_2: +V48_2_P -V48_2_N
differential pair V48_1: +V48_1_P -V48_1_N
differential pair HG1A: +HG1A_P -HG1A_N
differential pair HG2A: +HG2A_P -HG2A_N

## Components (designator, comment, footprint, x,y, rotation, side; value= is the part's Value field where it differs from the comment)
C1 "RT201C476MAJ10" AVX-ST20-J10 -950,1200 r180 top
C2 "C0805C221J1GACTU" 0805_HV -3670,-210 r180 top
C3 "12061C153JAT2A" 1206 -2650,1900 r90 top
C4 "08055C104KAT2A" 0805_HV -2780,1835 r180 top
C5 "08053C104KAT2A" 0805_HV 1335,2105 r0 top
C6 "C2012X7R1E474K" 0805_HV -1795,1575 r270 top
C7 "C2012X7R1E105K" 0805_HV -1795,1425 r270 top
C8 "RT203C227MAJ10" AVX-ST20-J10 2150,275 r90 top
C9 "08055A221JAT2A" 0805_HV -3420,-895 r0 top
C10 "C2012X7R1E105K" 0805_HV -1795,1275 r90 top
C11 "08053C104KAT2A" 0805_HV 1340,-1900 r0 top
C12 "C2012X7R1E474K" 0805_HV -1795,1130 r90 top
C13 "C0805C223K5RACTU" 0805_HV -3030,-675 r270 top
C14 "08053C104KAT2A" 0805_HV -1795,975 r270 top
C15 "CGA5L2X7R2A684K160AA" 1206_190 -2315,790 r270 top
C16 "C3216X7R2A334K130AA" 1206 -2730,770 r270 top
C17 "08055C104KAT2A" 0805_HV -2870,815 r0 top
C18 "C0805C223K5RACTU" 0805_HV -2055,725 r0 top
C19 "RT201C476MAJ10" AVX-ST20-J10 -950,-1200 r180 top
C20 "12061C153JAT2A" 1206 -2650,-650 r90 top
C21 "08055C104KAT2A" 0805_HV -2780,-715 r180 top
C22 "C2012X7R1E474K" 0805_HV -1795,-975 r270 top
C23 "C2012X7R1E105K" 0805_HV -1795,-1125 r270 top
C24 "RT203C227MAJ10" AVX-ST20-J10 2150,-275 r270 top
C25 "C2012X7R1E105K" 0805_HV -1795,-1275 r90 top
C26 "C2012X7R1E474K" 0805_HV -1795,-1420 r90 top
C27 "08053C104KAT2A" 0805_HV -1795,-1575 r270 top
C28 "CGA5L2X7R2A684K160AA" 1206_190 -2315,-1760 r270 top
C29 "08055C103JAT2A" 0805_HV -3470,2530 r180 top
C30 "GRM31CR71E106KA12L" 1206 -3330,2660 r270 top
C31 "GRM31CR71E106KA12L" 1206 -3620,2675 r270 top
C32 "C3216X7R2A334K130AA" 1206 -2730,-1780 r270 top
C33 "08055C104KAT2A" 0805_HV -2870,-1735 r0 top
C35 "EMK212BB7106MG-T" 0805_145 -3445,2055 r180 top
C36 "GRM31CR71E106KA12L" 1206 -3620,2055 r0 top
C37 "08055A330JAT2A" 0805_HV -3085,-385 r0 top
C38 "08055A330JAT2A" 0805_HV -2560,-1150 r180 top
C39 "12061C153JAT2A" 1206 -2300,1900 r90 top
C40 "12061C153JAT2A" 1206 -2300,-650 r90 top
C41 "08055A101JAT2A" 0805_HV -1645,-1725 r180 top
C42 "EGPA800ELL681MM30S" GPA_1800x3000 -3810,850 r270 top
D1 "1N4148W-7-F" SOD-123 -3435,-165 r270 top
D2 "1N4148W-7-F" SOD-123 -3440,-1230 r180 top
D3 "1N4148W-7-F" SOD-123 -3175,2180 r90 top
F1 "SSQ 12" SSQ -3555,1800 r180 top
F2 "0456030.ER" 456 3130,460 r180 top
F3 "SSQ 12" SSQ -2215,-2040 r0 top
F4 "0456030.ER" 456 3060,-950 r180 top
FID1 "Fiducial" Fiducial10-20 -3305,2975 r0 top
FID2 "Fiducial" Fiducial10-20 -3725,-2920 r0 top
FID3 "Fiducial" Fiducial10-20 3475,-2925 r0 top
FID4 "Fiducial" Fiducial10-20 -3305,2975 r180 bottom
FID5 "Fiducial" Fiducial10-20 3475,-2925 r180 bottom
FID6 "Fiducial" Fiducial10-20 -3725,-2920 r180 bottom
H1 "NY PMS 440 0025 PH" "NY PMS 440 0025 PH" -4225,2915 r0 top locked
H2 "NY PMS 440 0025 PH" "NY PMS 440 0025 PH" 3935,2915 r0 top locked
H3 "NY PMS 440 0025 PH" "NY PMS 440 0025 PH" -4225,-2925 r0 top locked
H4 "NY PMS 440 0025 PH" "NY PMS 440 0025 PH" 3935,-2925 r0 top locked
H5 "1902C" Keystone_1902C -4225,2915 r180 bottom
H6 "1902C" Keystone_1902C 3935,2915 r180 bottom
H7 "1902C" Keystone_1902C -4225,-2925 r180 bottom locked
H8 "1902C" Keystone_1902C 3935,-2925 r180 bottom locked
H9 "RM3X12MM 2701" APM_RM3X12MM_2701 250,2355 r0 top locked
H10 "RM3X12MM 2701" APM_RM3X12MM_2701 1100,2355 r0 top locked
H11 "RM3X12MM 2701" APM_RM3X12MM_2701 0,1300 r0 top locked
H12 "RM3X12MM 2701" APM_RM3X12MM_2701 1100,1300 r0 top locked
H13 "RM3X12MM 2701" APM_RM3X12MM_2701 -450,400 r0 top locked
H14 "RM3X12MM 2701" APM_RM3X12MM_2701 1900,2400 r0 top locked
H15 "RM3X12MM 2701" APM_RM3X12MM_2701 250,250 r0 top locked
H16 "RM3X12MM 2701" APM_RM3X12MM_2701 1100,250 r0 top locked
H17 "RM3X12MM 2701" APM_RM3X12MM_2701 -1900,2400 r0 top locked
H18 "RM3X12MM 2701" APM_RM3X12MM_2701 -450,2190 r0 top locked
H19 "RM3X12MM 2701" APM_RM3X12MM_2701 250,-2350 r0 top locked
H20 "RM3X12MM 2701" APM_RM3X12MM_2701 1100,-2350 r0 top locked
H21 "RM3X12MM 2701" APM_RM3X12MM_2701 0,-1300 r0 top locked
H22 "RM3X12MM 2701" APM_RM3X12MM_2701 1100,-1300 r0 top locked
H23 "RM3X12MM 2701" APM_RM3X12MM_2701 -450,-320 r0 top locked
H24 "RM3X12MM 2701" APM_RM3X12MM_2701 1900,-2400 r0 top locked
H25 "RM3X12MM 2701" APM_RM3X12MM_2701 250,-250 r0 top locked
H26 "RM3X12MM 2701" APM_RM3X12MM_2701 1100,-250 r0 top locked
H27 "RM3X12MM 2701" APM_RM3X12MM_2701 -1900,-2400 r0 top locked
H28 "RM3X12MM 2701" APM_RM3X12MM_2701 -450,-2190 r0 top locked
H50 "NONE" "HOLE INDUCTOR" 1980,1450 r0 top locked
H51 "NONE" "HOLE INDUCTOR" 1980,-1450 r0 top locked
H64 "HS-5.4-5.4-1.4-01" Custom_HS-5_4-5_4-1_4-01 0,0 r180 bottom
J1 "PJ-102A" PJ-102A -3985,2400 r180 top
J2 "22-27-2031" MOLEX_22-27-2031 -3655,2990 r180 bottom
J3 "TMDX28069USB_HALF ONE" Samtec_SSW-108-01-x-D -3680,-640 r180 top
J4 "TMDX28069USB_HALF TWO" Samtec_SSW-108-01-x-D -3680,-440 r180 top
L1 "SER2918H-682KL" SER2918 2225,1450 r0 top locked
L2 "SER2918H-682KL" SER2918 2225,-1450 r0 top locked
LBL1 "Size: 0.65\" x 0.20 \"" Label_650x200 -3015,-2590 r90 top
Logo1 "Texas Instruments" TI_Symbol_Overlay_Medium 3230,2040 r0 top
Logo2 "Pb-Free Symbol" Pb-Free_Overlay_Small -460,-2515 r0 top
LOGO3 "DANGER HIGH VOLTAGE" IEC_HighVoltage_Small -2908,1484 r0 top
Q1 "BSC123N08NS3 G" "PG-TDSON-8 WITH VIAS"#1 100,1900 r90 top
Q2 "BSC123N08NS3 G" "PG-TDSON-8 WITH VIAS"#1 600,1900 r90 top
Q3 "BSC123N08NS3 G" "PG-TDSON-8 WITH VIAS"#1 1100,1900 r90 top
Q4 "NX3020NAKW,115" SOT-323 -3815,-180 r0 top
Q5 "FJV1845FMTF" SOT-23 -2670,1715 r0 top
Q6 "BSC123N08NS3 G" "PG-TDSON-8 WITH VIAS"#2 -410,1565 r0 top
Q7 "BSC123N08NS3 G" "PG-TDSON-8 WITH VIAS"#2 -405,1080 r0 top
Q8 "BSC123N08NS3 G" "PG-TDSON-8 WITH VIAS"#2 100,800 r90 top
Q9 "BSC123N08NS3 G" "PG-TDSON-8 WITH VIAS"#2 600,800 r90 top
Q10 "BSC123N08NS3 G" "PG-TDSON-8 WITH VIAS"#2 1100,800 r90 top
Q11 "NX3020NAKW,115" SOT-323 -3315,-1105 r180 top
Q12 "FJV1845FMTF" SOT-23 -2860,975 r90 top
Q13 "BSC123N08NS3 G" "PG-TDSON-8 WITH VIAS"#2 100,-1900 r270 top
Q14 "BSC123N08NS3 G" "PG-TDSON-8 WITH VIAS"#2 600,-1900 r270 top
Q15 "BSC123N08NS3 G" "PG-TDSON-8 WITH VIAS"#2 1100,-1900 r270 top
Q16 "FJV1845FMTF" SOT-23 -2670,-835 r0 top
Q17 "BSC123N08NS3 G" "PG-TDSON-8 WITH VIAS"#2 -415,-1340 r0 top
Q18 "BSC123N08NS3 G" "PG-TDSON-8 WITH VIAS"#2 -415,-840 r0 top
Q19 "BSC123N08NS3 G" "PG-TDSON-8 WITH VIAS"#2 100,-800 r270 top
Q20 "BSC123N08NS3 G" "PG-TDSON-8 WITH VIAS"#2 600,-800 r270 top
Q21 "BSC123N08NS3 G" "PG-TDSON-8 WITH VIAS"#2 1100,-800 r270 top
Q22 "FJV1845FMTF" SOT-23 -2860,-1575 r90 top
R1 "LVK24R012FER" LVK24 -2550,570 r0 top
R2 "CRCW080539K2FKEA" 0805_HV -4320,1030 r90 top
R3 "CRCW08052K00FKEA" 0805_HV -3540,-195 r270 top
R4 "CRCW08053R01FKEA" 0805_HV 285,1830 r270 top
R5 "CRCW08053R01FKEA" 0805_HV 785,1830 r90 top
R6 "CRCW08053R01FKEA" 0805_HV 1285,1830 r90 top
R7 "CRCW0805105RFKEA" 0805_HV -2530,1950 r90 top
R8 "CRCW0805105RFKEA" 0805_HV -2420,1950 r90 top
R9 "CRCW080510K0FKEA" 0805_HV -3700,-1205 r0 top
R10 "CRCW080510K0FKEA" 0805_HV -3700,-1005 r0 top
R11 "CRCW08059K76FKEA" 0805_HV -2675,1585 r180 top
R12 "CRCW08051R00FKEA" 0805_HV -1630,1550 r0 top
R13 "WSL27262L000FEB" "RES_WSL2726 WITH VIAS" 1705,650 r90 top
R14 "CRCW08058K25FKEA" 0805_HV 3225,-1245 r90 top
R15 "CRCW08051R00FKEA" 0805_HV -1630,1400 r0 top
R16 "CRCW1206499RFKEA" 1206 3355,-1265 r90 top
R17 "CRCW08052K00FKEA" 0805_HV -3420,-995 r180 top
R18 "CRCW080510K0FKEA" 0805_HV -3700,-1105 r0 top
R19 "CRCW080510K0FKEA" 0805_HV -3700,-905 r0 top
R20 "CRCW08051R00FKEA" 0805_HV -1630,1300 r0 top
R21 "CRCW08053R01FKEA" 0805_HV 790,725 r90 top
R22 "CRCW08053R01FKEA" 0805_HV -480,890 r0 top
R23 "CRCW08053R01FKEA" 0805_HV 285,725 r90 top
R24 "CRCW08053R01FKEA" 0805_HV 1290,725 r90 top
R25 "CRCW08053R01FKEA" 0805_HV -480,1380 r180 top
R26 "CRCW08051R00FKEA" 0805_HV -1630,1150 r0 top
R27 "CRCW08054K99FKEA" 0805_HV -3135,-675 r90 top
R28 "CRCW0805196RFKEA" 0805_HV -2500,790 r270 top
R29 "CRCW0805196RFKEA" 0805_HV -2460,945 r180 top
R30 "CRCW08051R00FKEA" 0805_HV -3330,-195 r90 top
R31 "CRCW08054K99FKEA" 0805_HV -3085,-495 r180 top
R32 "CRCW0805392RFKEA" 0805_HV -2615,790 r270 top
R33 "CRCW08059K76FKEA" 0805_HV -2690,925 r180 top
R34 "CRCW08054K99FKEA" 0805_HV -2055,820 r180 top
R35 "CRCW08054K99FKEA" 0805_HV -2560,-1060 r0 top
R36 "LVK24R012FER" LVK24 -2550,-1980 r0 top
R37 "CRCW08053R01FKEA" 0805_HV 415,-1830 r270 top
R38 "CRCW08053R01FKEA" 0805_HV 915,-1830 r270 top
R39 "CRCW0805105RFKEA" 0805_HV -2530,-600 r90 top
R40 "CRCW0805105RFKEA" 0805_HV -2420,-600 r90 top
R41 "CRCW08053R01FKEA" 0805_HV -85,-1830 r90 top
R42 "CRCW08059K76FKEA" 0805_HV -2675,-965 r180 top
R43 "CRCW08051R00FKEA" 0805_HV -1630,-1000 r0 top
R44 "WSL27262L000FEB" "RES_WSL2726 WITH VIAS" 1705,-650 r90 top
R45 "CRCW08051R00FKEA" 0805_HV -1630,-1150 r0 top
R46 "CRCW08051R00FKEA" 0805_HV -1630,-1250 r0 top
R47 "CRCW08053R01FKEA" 0805_HV -485,-1025 r0 top
R48 "CRCW08053R01FKEA" 0805_HV -85,-730 r270 top
R49 "CRCW08053R01FKEA" 0805_HV 415,-730 r270 top
R50 "CRCW08053R00JNEA" 0805_HV 915,-730 r270 top
R51 "CRCW08053R01FKEA" 0805_HV -485,-1525 r0 top
R52 "CRCW08051R00FKEA" 0805_HV -1630,-1400 r0 top
R54 "CRCW0805196RFKEA" 0805_HV -2500,-1760 r270 top
R55 "CRCW0805196RFKEA" 0805_HV -2460,-1605 r180 top
R57 "CRCW0805392RFKEA" 0805_HV -2615,-1760 r270 top
R58 "CRCW0805100KFKEA" 0805_HV -3175,2360 r270 top
R59 "CRCW08051K00FKEA" 0805_HV -1825,-1725 r180 top
R61 "CRCW08059K76FKEA" 0805_HV -2690,-1625 r180 top
R63 "CRCW0805105RFKEA" 0805_HV -2530,1750 r90 top
R64 "CRCW0805105RFKEA" 0805_HV -2420,1750 r90 top
R65 "CRCW0805105RFKEA" 0805_HV -2530,-800 r90 top
R66 "CRCW0805105RFKEA" 0805_HV -2420,-800 r90 top
T1 "CB35-36-CY" CB35-36-CY -3880,1475 r0 top
T2 "CB35-36-CY" CB35-36-CY -3880,225 r0 top
T3 "CB70-14-CY" CB70-14-CY 3730,-975 r180 top
T4 "CB70-14-CY" CB70-14-CY 3070,15 r180 top
TP1 "5015" Testpoint_Keystone_Miniature -4090,1825 r0 top
TP2 "5015" Testpoint_Keystone_Miniature -3840,1825 r0 top
TP3 "5015" Testpoint_Keystone_Miniature -3210.3,1789.56 r90 top
TP4 "5015" Testpoint_Keystone_Miniature -1630,1020 r0 top
TP5 "5015" Testpoint_Keystone_Miniature -4080,-130 r0 top
TP6 "5015" Testpoint_Keystone_Miniature -1630,1715 r0 top
TP7 "5015" Testpoint_Keystone_Miniature 2185,755 r0 top
TP8 "5015" Testpoint_Keystone_Miniature 2900,675 r0 top
TP9 "5015" Testpoint_Keystone_Miniature 3350,675 r0 top
TP10 "5015" Testpoint_Keystone_Miniature -1630,750 r0 top
TP11 "5015" Testpoint_Keystone_Miniature -4175.04,2035.04 r0 top
TP12 "5015" Testpoint_Keystone_Miniature -2930,-870 r270 top
TP13 "5015" Testpoint_Keystone_Miniature -2895,-355 r0 top
TP14 "5015" Testpoint_Keystone_Miniature -3165,-1520 r180 top
TP15 "5015" Testpoint_Keystone_Miniature -1740,-1840 r180 top
TP16 "5015" Testpoint_Keystone_Miniature -2195,810 r270 top
TP17 "5015" Testpoint_Keystone_Miniature -2540,-1400 r0 top
TP18 "5015" Testpoint_Keystone_Miniature -4320,850 r0 top
TP19 "5015" Testpoint_Keystone_Miniature -2800,-1090 r0 top
TP20 "5015" Testpoint_Keystone_Miniature -4320,615 r0 top
TP21 "5015" Testpoint_Keystone_Miniature -2600,1130 r0 top
TP22 "5015" Testpoint_Keystone_Miniature -4150,1175 r90 top
TP23 "5015" Testpoint_Keystone_Miniature -2455,-2260 r90 top
TP24 "5015" Testpoint_Keystone_Miniature -4120,480 r0 top
TP25 "5015" Testpoint_Keystone_Miniature -4320,-1200 r0 top
TP26 "5015" Testpoint_Keystone_Miniature -4320,-1400 r0 top
TP27 "5015" Testpoint_Keystone_Miniature -1630,-1530 r0 top
TP28 "5015" Testpoint_Keystone_Miniature -1630,-835 r0 top
TP29 "5015" Testpoint_Keystone_Miniature 2450,-750 r0 top
TP30 "5015" Testpoint_Keystone_Miniature 2710,-955 r90 top
TP31 "5015" Testpoint_Keystone_Miniature 3970,675 r0 top
TP32 "5015" Testpoint_Keystone_Miniature -1630,-560 r0 top
TP33 "5015" Testpoint_Keystone_Miniature -2970,2675 r0 top
TP34 "5015" Testpoint_Keystone_Miniature -2965,2505 r0 top
TP35 "5015" Testpoint_Keystone_Miniature -3865,2735 r0 top
TP36 "5015" Testpoint_Keystone_Miniature -2955,2115 r0 top
TP37 "5015" Testpoint_Keystone_Miniature -2225,2975 r0 top
TP38 "5015" Testpoint_Keystone_Miniature -1475,2975 r0 top
TP39 "5015" Testpoint_Keystone_Miniature -725,2975 r180 top
TP40 "5015" Testpoint_Keystone_Miniature 25,2975 r0 top
TP41 "5015" Testpoint_Keystone_Miniature 775,2975 r0 top
TP42 "5015" Testpoint_Keystone_Miniature 1475,2975 r180 top
TP43 "5015" Testpoint_Keystone_Miniature 2255,2975 r180 top
TP44 "5015" Testpoint_Keystone_Miniature -2225,-2975 r180 top
TP45 "5015" Testpoint_Keystone_Miniature -1500,-2975 r180 top
TP46 "5015" Testpoint_Keystone_Miniature -750,-2975 r180 top
TP47 "5015" Testpoint_Keystone_Miniature 0,-2975 r180 top
TP48 "5015" Testpoint_Keystone_Miniature 750,-2975 r180 top
TP49 "5015" Testpoint_Keystone_Miniature 1500,-2975 r180 top
TP50 "5015" Testpoint_Keystone_Miniature 2255,-2975 r180 top
TP51 "5015" Testpoint_Keystone_Miniature -4320,-1000 r0 top
TP52 "5015" Testpoint_Keystone_Miniature -4320,-1600 r0 top
TP53 "5015" Testpoint_Keystone_Miniature 3970,1310 r180 top
TP54 "5015" Testpoint_Keystone_Miniature 3970,960 r180 top
TP55 "5015" Testpoint_Keystone_Miniature 3970,-2070 r180 top
TP56 "5015" Testpoint_Keystone_Miniature 3970,-1740 r180 top
U1 "SM72295MA" SO28_DW -2130,1275 r0 top locked
U2 "TMP103AYFF" YFF0004AAAA 1332.13,1990 r0 top
U3 "TMP103BYFF" YFF0004AAAA 1340,-2000 r0 top
U4 "SM72295MA" SO28_DW -2130,-1275 r0 top locked
U5 "LP2985-10DBVT" DBV0005A_N -3475,2665 r0 top
U6 "TPS7A4533DCQT" DCQ0006A_N -3520,2290 r90 top
ZZ1 "This Assembly Note is for PCB labels only" AssemblyNoteLabel -4525,4675 r0 top
ZZ2 "These assemblies are ESD sensitive, ESD precautions shall be observed." AssemblyNote -4525,4550 r0 top
ZZ3 "These assemblies must be clean and free from flux and all contaminants. Use of no clean flux is not acceptable." AssemblyNote -4525,4450 r0 top
ZZ4 "These assemblies must comply with workmanship standards IPC-A-610 Class 2, unless otherwise specified." AssemblyNote -4525,4325 r0 top
ZZ5 "These assemblies must comply with workmanship standards IPC-A-610 Class 2, unless otherwise specified." AssemblyNote -4500,4200 r0 top
ZZ6 "These assemblies must comply with workmanship standards IPC-A-610 Class 2, unless otherwise specified." AssemblyNote -4500,4050 r0 top
ZZ7 "These assemblies must comply with workmanship standards IPC-A-610 Class 2, unless otherwise specified." AssemblyNote -4500,3900 r0 top
ZZ8 "These assemblies must comply with workmanship standards IPC-A-610 Class 2, unless otherwise specified." AssemblyNote -4500,3775 r0 top

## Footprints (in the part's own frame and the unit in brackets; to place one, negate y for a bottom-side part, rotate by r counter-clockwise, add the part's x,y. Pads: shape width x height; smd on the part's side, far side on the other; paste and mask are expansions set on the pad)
456 [mm] "LITTELFUSE 456 SERIES FUSE"
  rect 3.25x3.44 smd: 1(-4.675,0) 2(4.675,0)
  silkscreen extent -6.6,-2 6.6,2, body extent -6.6,-2 6.6,2, height 3.12
0805_145 [mm] "0805 / 1.45mm height"
  rect 1.15x1.45 smd: 1(-0.9,0) 2(0.9,0)
  silkscreen extent -0.1,-0.8 0.1,0.8, body extent -1.1,-0.72 1.1,0.72, height 1.45
0805_HV [mil] "0805 with 30mil clearance between pads"
  rect 50x63 smd: 1(-40,0) 2(40,0)
  silkscreen extent -74,-40 74,40, body extent -43,-29 43,29, height 43
1206 [mm] "1206 from SM-752 data"
  rect 1.3x1.85 smd: 1(-1.45,0) 2(1.45,0)
  silkscreen extent -2.4,-1.21 2.4,1.21, body extent -1.7,-0.9 1.7,0.9, height 1.35
1206_190 [mm] "1206_190"
  rect 1.1x1.6 smd: 1(-1.7,0) 2(1.7,0)
  silkscreen extent -0.9,-1 0.9,1, body extent -1.75,-0.95 1.75,0.95, height 1.9
APM_RM3X12MM_2701 [mm] "Screw, Dia 6.7mm, Length 12mm, TH"
  round 5.5 hole 3.6: ""(0,0)
  silkscreen extent -3.35,-3.35 3.35,3.35, body extent -3.36,-3.36 3.36,3.36, height 2.4
AssemblyNote [mil] "Assembly Note"
AssemblyNoteLabel [mil] "Assembly Note for PCB Labels"
AVX-ST20-J10 [mil] "SMD, Body 1075x300mil"
  rrect20% 110x950 smd: 1(-97.5,0) 2(97.5,0)
  silkscreen extent -168,-538 168,538, body extent -150,-538 150,538, height 285
CB35-36-CY [mil] "Terminal 50A Lug"
  rect 550x380 hole 188 copper offset -45,0 paste-190: 1(0,0)
  body extent -960,-189 230,191, height 614
CB70-14-CY [mil] "Terminal 90A Lug"
  rect 680x500 hole 250 copper offset -90,0 paste-250: 1(0,0)
  body extent -1300,-260 250,260, height 714
Custom_HS-5_4-5_4-1_4-01 [mil] "Heat Sink 5.4 x 5.4 x 1.4"
  round 60 on Bottom Overlay: 0(0,0)
  silkscreen extent -2688,-2688 2688,2688, body extent -2687,-2688 2688,2687, height 1375
DBV0005A_N [mm] "SOT23, 5-Leads, Body 2.9x1.6mm, Pitch 0.95mm, Lead Span 2.8mm, IPC Medium Density"
  rect 1.1x0.65 smd: 1(-1.2,0.95) 2(-1.2,0) 3(-1.2,-0.95) 4(1.2,-0.95) 5(1.2,0.95)
  silkscreen extent -0.25,-1.55 0.25,1.55, body extent -1.42,-1.46 1.42,1.46, height 1.08
DCQ0006A_N [mm] "SOT223, 6-Leads, Body 6.6x7.3mm (max), Pitch 1.27mm, IPC Medium Density"
  rect 2.2x0.65 smd: 1(-3,2.54) 2(-3,1.27) 3(-3,0) 4(-3,-1.27) 5(-3,-2.54)
  rect 2.2x3.3 smd: 6(3,0)
  silkscreen extent -1.5,-3.27 1.5,3.27, body extent -3.48,-3.25 3.48,3.25, height 1.64
Fiducial10-20 [mm]
  round 1 smd mask+0.5: 1(0,0)
  Top Layer keep-out circle w1.178: c0,0 r0.5
GPA_1800x3000 [mm] "TH, 2-Leads, Dia 18mm, Lead Spacing 7.5mm"
  rect 1.55x1.55 hole 1.05: 1(-3.75,0)
  round 1.55 hole 1.05: 2(3.75,0)
  silkscreen extent -9.25,-9.25 9.25,9.25, body extent -9.18,-9.24 9.22,9.24, height 31.5
"HOLE INDUCTOR" [mm] "M3 X0.5 HOLE NO METAL"
  round 10 hole 7.2: 1(0,0)
  silkscreen extent -5.3,-5.3 5.3,5.3, body extent -5.45,-5.4 5.5,5.4, height 2.5
IEC_HighVoltage_Small [mil]
  silkscreen extent -107,-88 107,97
Keystone_1902C [mil] "Hex Standoff, 4-40 threaded, nylon"
  body extent -145,-126 146,126, height 501
Label_650x200 [mil] "Thermal Transfer Label"
  silkscreen extent -325,-100 325,100, body extent -326,-101 326,101, height 1
LVK24 [mm] "Ohmite recommended land pattern"
  rect 3.25x1.9 smd: 1(-2.625,-1.25) 2(2.625,-1.25) 3(-2.625,1.25) 4(2.625,1.25)
  silkscreen extent -0.67,-1.96 0.67,1.96, body extent -3.3,-1.71 3.3,1.71, height 0.7
MOLEX_22-27-2031 [mm] "MOLEX"
  rect 1.8x1.8 hole 1.2: 1(-2.54,0)
  round 1.8 hole 1.2: 2(0,0) 3(2.54,0)
  silkscreen extent -4.37,-2.9 3.81,2.96, body extent -3.81,-2.9 3.81,2.9, height 11.72
"NY PMS 440 0025 PH" [mm] "4-40 nylon screw and mounting hole"
  round 8 hole 3.2: 1(0,0)
  body extent -3.3,-3.3 3.3,3.3, height 2.69
Pb-Free_Overlay_Small [mil]
  silkscreen extent -46,-46 46,46
"PG-TDSON-8 WITH VIAS"#1 [mm] "Infineon recommended land pattern"
  rect 1.2x0.65 smd: 1(-2.825,1.905) 2(-2.825,0.635) 3(-2.825,-0.635) 4(-2.825,-1.905)
  rect 0.5x0.7 smd: 5(3.175,-2) 6(3.175,-0.675) 7(3.175,0.675) 8(3.175,2)
  rect 4.5x4.7 smd paste-2.25: 9(0.762,0)
  silkscreen extent -3.74,-3 3.74,3, body extent -3.17,-2.89 3.17,2.9, height 1.1
"PG-TDSON-8 WITH VIAS"#2 [mm] "Infineon recommended land pattern"
  rect 1.2x0.65 smd: 1(-2.825,1.905) 2(-2.825,0.635) 3(-2.825,-0.635) 4(-2.825,-1.905)
  rect 0.5x0.7 smd: 5(3.175,-2) 6(3.175,-0.675) 7(3.175,0.675) 8(3.175,2)
  rect 4.5x4.7 smd paste-2.25: 9(0.675,0)
  silkscreen extent -3.74,-3 3.74,3, body extent -3.17,-2.89 3.17,2.9, height 1.1
PJ-102A [mm] "CU INC PJ-102A"
  round 3 hole 1.4: 1(-3,0) 2(3,0) 3(0,4.7)
  silkscreen extent -3,-5 12,5, body extent -3,-5 12,5, height 11
"RES_WSL2726 WITH VIAS" [mm] "Vishay Dale"
  rect 2.44x5.6 smd: 1(-2.48,-2.07) 2(2.48,-2.065)
  rect 2.44x0.89 smd: 3(-2.48,2.065) 4(2.48,2.07)
  body extent -3.55,-4.45 3.55,2.45, height 3.22
Samtec_SSW-108-01-x-D [mm] "Receptacle, 2.54mm, 8x2, TH"
  rect 1.55x1.55 hole 1.04: 1(-8.89,1.27)
  round 1.55 hole 1.04: 2(-8.89,-1.27) 3(-6.35,1.27) 4(-6.35,-1.27) 5(-3.81,1.27) 6(-3.81,-1.27) 7(-1.27,1.27) 8(-1.27,-1.27) 9(1.27,1.27) 10(1.27,-1.27) 11(3.81,1.27) 12(3.81,-1.27) 13(6.35,1.27) 14(6.35,-1.27) 15(8.89,1.27) 16(8.89,-1.27)
  silkscreen extent -10.41,-2.48 10.41,3, body extent -10.41,-2.48 10.41,2.48, height 8.51
SER2918 [mm] "Coilcraft recommended land pattern.  Document 644-2, rev 12/12/08"
  rect 5.59x5.33 smd: 1(-14.355,5.075) 2(-14.355,-5.075)
  rect 5.28x6.35 smd: 3(7.72,0)
  silkscreen extent -10,-14.5 10,14.5, body extent -16.8,-13.95 11.03,13.95, height 17.78
SO28_DW [mil]
  rect 80x30 smd: 1(-185,325) 2(-185,275) 3(-185,225) 4(-185,175) 5(-185,125) 6(-185,75) 7(-185,25) 8(-185,-25) 9(-185,-75) 10(-185,-125) 11(-185,-175) 12(-185,-225) 13(-185,-275) 14(-185,-325) 15(185,-325) 16(185,-275) 17(185,-225) 18(185,-175) 19(185,-125) 20(185,-75) 21(185,-25) 22(185,25) 23(185,75) 24(185,125) 25(185,175) 26(185,225) 27(185,275) 28(185,325)
  silkscreen extent -290,350 -250,390
SOD-123 [mm] "On Semi recommended land pattern"
  rect 0.915x1.22 smd: 1(-1.637,0) 2(1.637,0)
  silkscreen extent -2.74,-1.17 2.03,1.17, body extent -1.93,-0.9 1.93,0.9, height 1.35
SOT-23 [mm] "SOT23, 3-Leads, Body 2.9x1.3mm, Pitch 0.95mm, Lead Span 2.5mm, IPC Medium Density"
  rrect50% 1x0.6 smd: 1(-1.2,0.95) 2(-1.2,-0.95) 3(1.2,0)
  silkscreen extent -1.63,-1.5 0.7,1.5, body extent -1.16,-1.45 1.21,1.45, height 1
SOT-323 [mm] "Zetex recommended land pattern.  March 2007"
  rect 0.8x0.6 smd: 1(-0.8,0.65) 2(-0.8,-0.65) 3(0.8,0)
  silkscreen extent -1.14,-1.22 0.77,1.22, body extent -1.13,-1.13 1.12,1.12, height 1.13
SSQ [mm] "BEL FUSE INC SSQ FUSE"
  rect 2x3.2 smd: 1(-2.5,0) 2(2.5,0)
  silkscreen extent -3.9,-2 4,2, body extent -3.9,-2 4,2, height 2.54
Testpoint_Keystone_Miniature [mil] "Miniature SMT test point"
  rect 135x70 smd: 1(0,0)
  silkscreen extent -78,-46 78,45, body extent -52,-20 52,20, height 61
TI_Symbol_Overlay_Medium [mil]
  silkscreen extent -124,-122 124,120
YFF0004AAAA [mm] "TI DSBGA 0.790x0.790mm"
  round 0.23 smd paste-0.13 mask+0.04: A1(-0.2,0.2) A2(0.2,0.2) B1(-0.2,-0.2) B2(0.2,-0.2)
  silkscreen extent -0.55,-0.55 0.55,0.55, body extent -0.39,-0.39 0.39,0.39, height 0.63

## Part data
C1 C19: "CAP, CERM, 47 µF, 100 V, +/- 20%, X7R, 1075x300mil"
C2: "CAP, CERM, 220 pF, 100 V, +/- 5%, C0G/NP0, 0805"
C3 C20 C39 C40: "CAP, CERM, 0.015 µF, 100 V, +/- 5%, X7R, 1206"
C4 C17 C21 C33: "CAP, CERM, 0.1 µF, 50 V, +/- 10%, X7R, 0805"
C5 C11 C14 C27: "CAP, CERM, 0.1 µF, 25 V, +/- 10%, X7R, 0805"
C6 C12 C22 C26: "CAP, CERM, 0.47 µF, 25 V, +/- 10%, X7R, 0805"
C7 C10 C23 C25: "CAP, CERM, 1 µF, 25 V, +/- 10%, X7R, 0805"
C8 C24: "CAP, CERM, 220 µF, 25 V, +/- 20%, X7R, 1075x300mil"
C9: "CAP, CERM, 220 pF, 50 V, +/- 5%, C0G/NP0, 0805"
C13 C18: "CAP, CERM, 0.022 µF, 50 V, +/- 10%, X7R, 0805"
C15 C28: "CAP, CERM, 0.68 µF, 100 V, +/- 10%, X7R, 1206_190"
C16 C32: "CAP, CERM, 0.33 µF, 100 V, +/- 10%, X7R, 1206"
C29: "CAP, CERM, 0.01 µF, 50 V, +/- 5%, X7R, 0805"
C30 C31 C36: "CAP, CERM, 10 µF, 25 V, +/- 10%, X7R, 1206"
C35: "CAP, CERM, 10 µF, 16 V, +/- 20%, X7R, 0805"
C37 C38: "CAP, CERM, 33 pF, 50 V, +/- 5%, C0G/NP0, 0805"
C41: "CAP, CERM, 100 pF, 50 V, +/- 5%, C0G/NP0, 0805"
C42: "CAP, AL, 680 µF, 80 V, +/- 20%, 0.041 ohm, TH"
D1 D2 D3: "Diode, Ultrafast, 100 V, 0.15 A, SOD-123"
F1 F3: "FUSE BOARD MNT 12A 125VAC 86VDC"
F2 F4: "FUSE BOARD MNT 30A 125VAC 72VDC"
FID1 FID2 FID3 FID4 FID5 FID6: "Fiducial mark.  There is nothing to buy or mount."
H1 H2 H3 H4: "Machine Screw, Round, #4-40 x 1/4, Nylon, Philips panhead"
H5 H6 H7 H8: "Standoff, Hex, 0.5\"L #4-40 Nylon"
H9 H10 H11 H12 H13 H14 H15 H16 H17 H18 H19 H20 H21 H22 H23 H24 H25 H26 H27 H28: "Machine Screw Pan PHILLIPS M3, TH"
H50 H51: library part "HOLE INDUCTOR", "HOLE INDUCTOR"
H64: "Heat Sink 5.4 x 5.4 x 1.4 Inch"
J1: "CONN JACK POWER 2.1MM PCB"
J2: "CONN HEADER 3POS .100 VERT TIN"
J3 J4: "DEV STICK USB PICCOLO F28069 HALF PART"
L1 L2: "Inductor, Shielded E Core, Ferrite, 6.8uH, 28A, 0.0026 ohm, SMD"
LBL1: library part THT-14-423-10, "Thermal Transfer Printable Labels, 0.650\" W x 0.200\" H - 10,000 per roll"
Logo1: library part TI_Logo, "Texas Instrument Corporate Signature"
Logo2: library part Pb-Free
LOGO3: library part IEC_HighVoltage, "IEC 61010-1 High Voltage Warning"
Q1 Q2 Q3 Q6 Q7 Q8 Q9 Q10 Q13 Q14 Q15 Q17 Q18 Q19 Q20 Q21: "MOSFET, N-CH, 80V, 55A, PG-TDSON-8"
Q4 Q11: "MOSFET, N-CH, 30 V, 0.18 A, SOT-323"
Q5 Q12 Q16 Q22: library part "FJV1845FMTF, Fairchild Semiconductor", "Transistor, NPN, 120 V, 0.05 A, SOT-23"
R1 R36: "RES, 0.012, 1%, 1 W, 2412"
R2: "RES, 39.2 k, 1%, 0.125 W, 0805"
R3 R17: "RES, 2.00 k, 1%, 0.125 W, 0805"
R4 R5 R6 R21 R22 R23 R24 R25 R37 R38 R41 R47 R48 R49 R51: "RES, 3.01, 1%, 0.125 W, 0805"
R7 R8 R39 R40 R63 R64 R65 R66: "RES, 105, 1%, 0.125 W, 0805"
R9 R10 R18 R19: "RES, 10.0 k, 1%, 0.125 W, 0805"
R11 R33 R42 R61: "RES, 9.76 k, 1%, 0.125 W, 0805"
R12 R15 R20 R26 R30 R43 R45 R46 R52: "RES, 1.00, 1%, 0.125 W, 0805"
R13 R44: "RES, 0.002, 1%, 3 W, 6.6x3x6.9mm"
R14: "RES, 8.25 k, 1%, 0.125 W, 0805"
R16: "RES, 499, 1%, 0.25 W, 1206"
R27 R31 R34 R35: "RES, 4.99 k, 1%, 0.125 W, 0805"
R28 R29 R54 R55: "RES, 196, 1%, 0.125 W, 0805"
R32 R57: "RES, 392, 1%, 0.125 W, 0805"
R50: "RES, 3.0, 5%, 0.125 W, 0805"
R58: "RES, 100 k, 1%, 0.125 W, 0805"
R59: "RES, 1.00 k, 1%, 0.125 W, 0805"
T1 T2: "Terminal 50A Lug"
T3 T4: "Terminal 90A Lug"
TP1 TP2 TP3 TP4 TP5 TP6 TP7 TP8 TP9 TP10 TP11 TP12 TP13 TP14 TP15 TP16 TP17 TP18 TP19 TP20 TP21 TP22 TP23 TP24 TP25 TP26 TP27 TP28 TP29 TP30 TP31 TP32 TP33 TP34 TP35 TP36 TP37 TP38 TP39 TP40 TP41 TP42 TP43 TP44 TP45 TP46 TP47 TP48 TP49 TP50 TP51 TP52 TP53 TP54 TP55 TP56: "Test Point, Miniature, SMT"
U1 U4: "IC, Photovoltaic Full Bridge Driver"
U2 U3: "Low-Power, Digital Temperature Sensor with Two-Wire Interface in WCSP, YFF0004AAAA"
U5: "Single Output Low Noise LDO, 150 mA, Fixed 10 V Output, 2.2 to 16 V Input, with Low IQ, 5-pin SOT-23 (DBV), -40 to 125 degC, Green (RoHS & no Sb/Br)"
U6: "Single Output Fast Transient Response LDO, 1.5 A, Fixed 3.3 V Output, 2.1 to 20 V Input, 6-pin SOT-223 (DCQ), -40 to 125 degC, Green (RoHS & no Sb/Br)"
ZZ1: library part AssemblyNoteLabel
ZZ2 ZZ3 ZZ4 ZZ5 ZZ6 ZZ7 ZZ8: library part AssemblyNote

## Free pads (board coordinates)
  round 60 hole 30: 0(-2695,2675) 0(0,0)
  round 30 smd: EndPad(-3175,2500) StartPad(-3330,2700)

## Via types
v1: diameter 22, hole 10, Top Layer to Bottom Layer, 518 vias
v2: diameter 30, hole 15, Top Layer to Bottom Layer, 479 vias
v3: diameter 50, hole 28, Top Layer to Bottom Layer, 303 vias
v4: diameter 32, hole 16, Top Layer to Bottom Layer, 172 vias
